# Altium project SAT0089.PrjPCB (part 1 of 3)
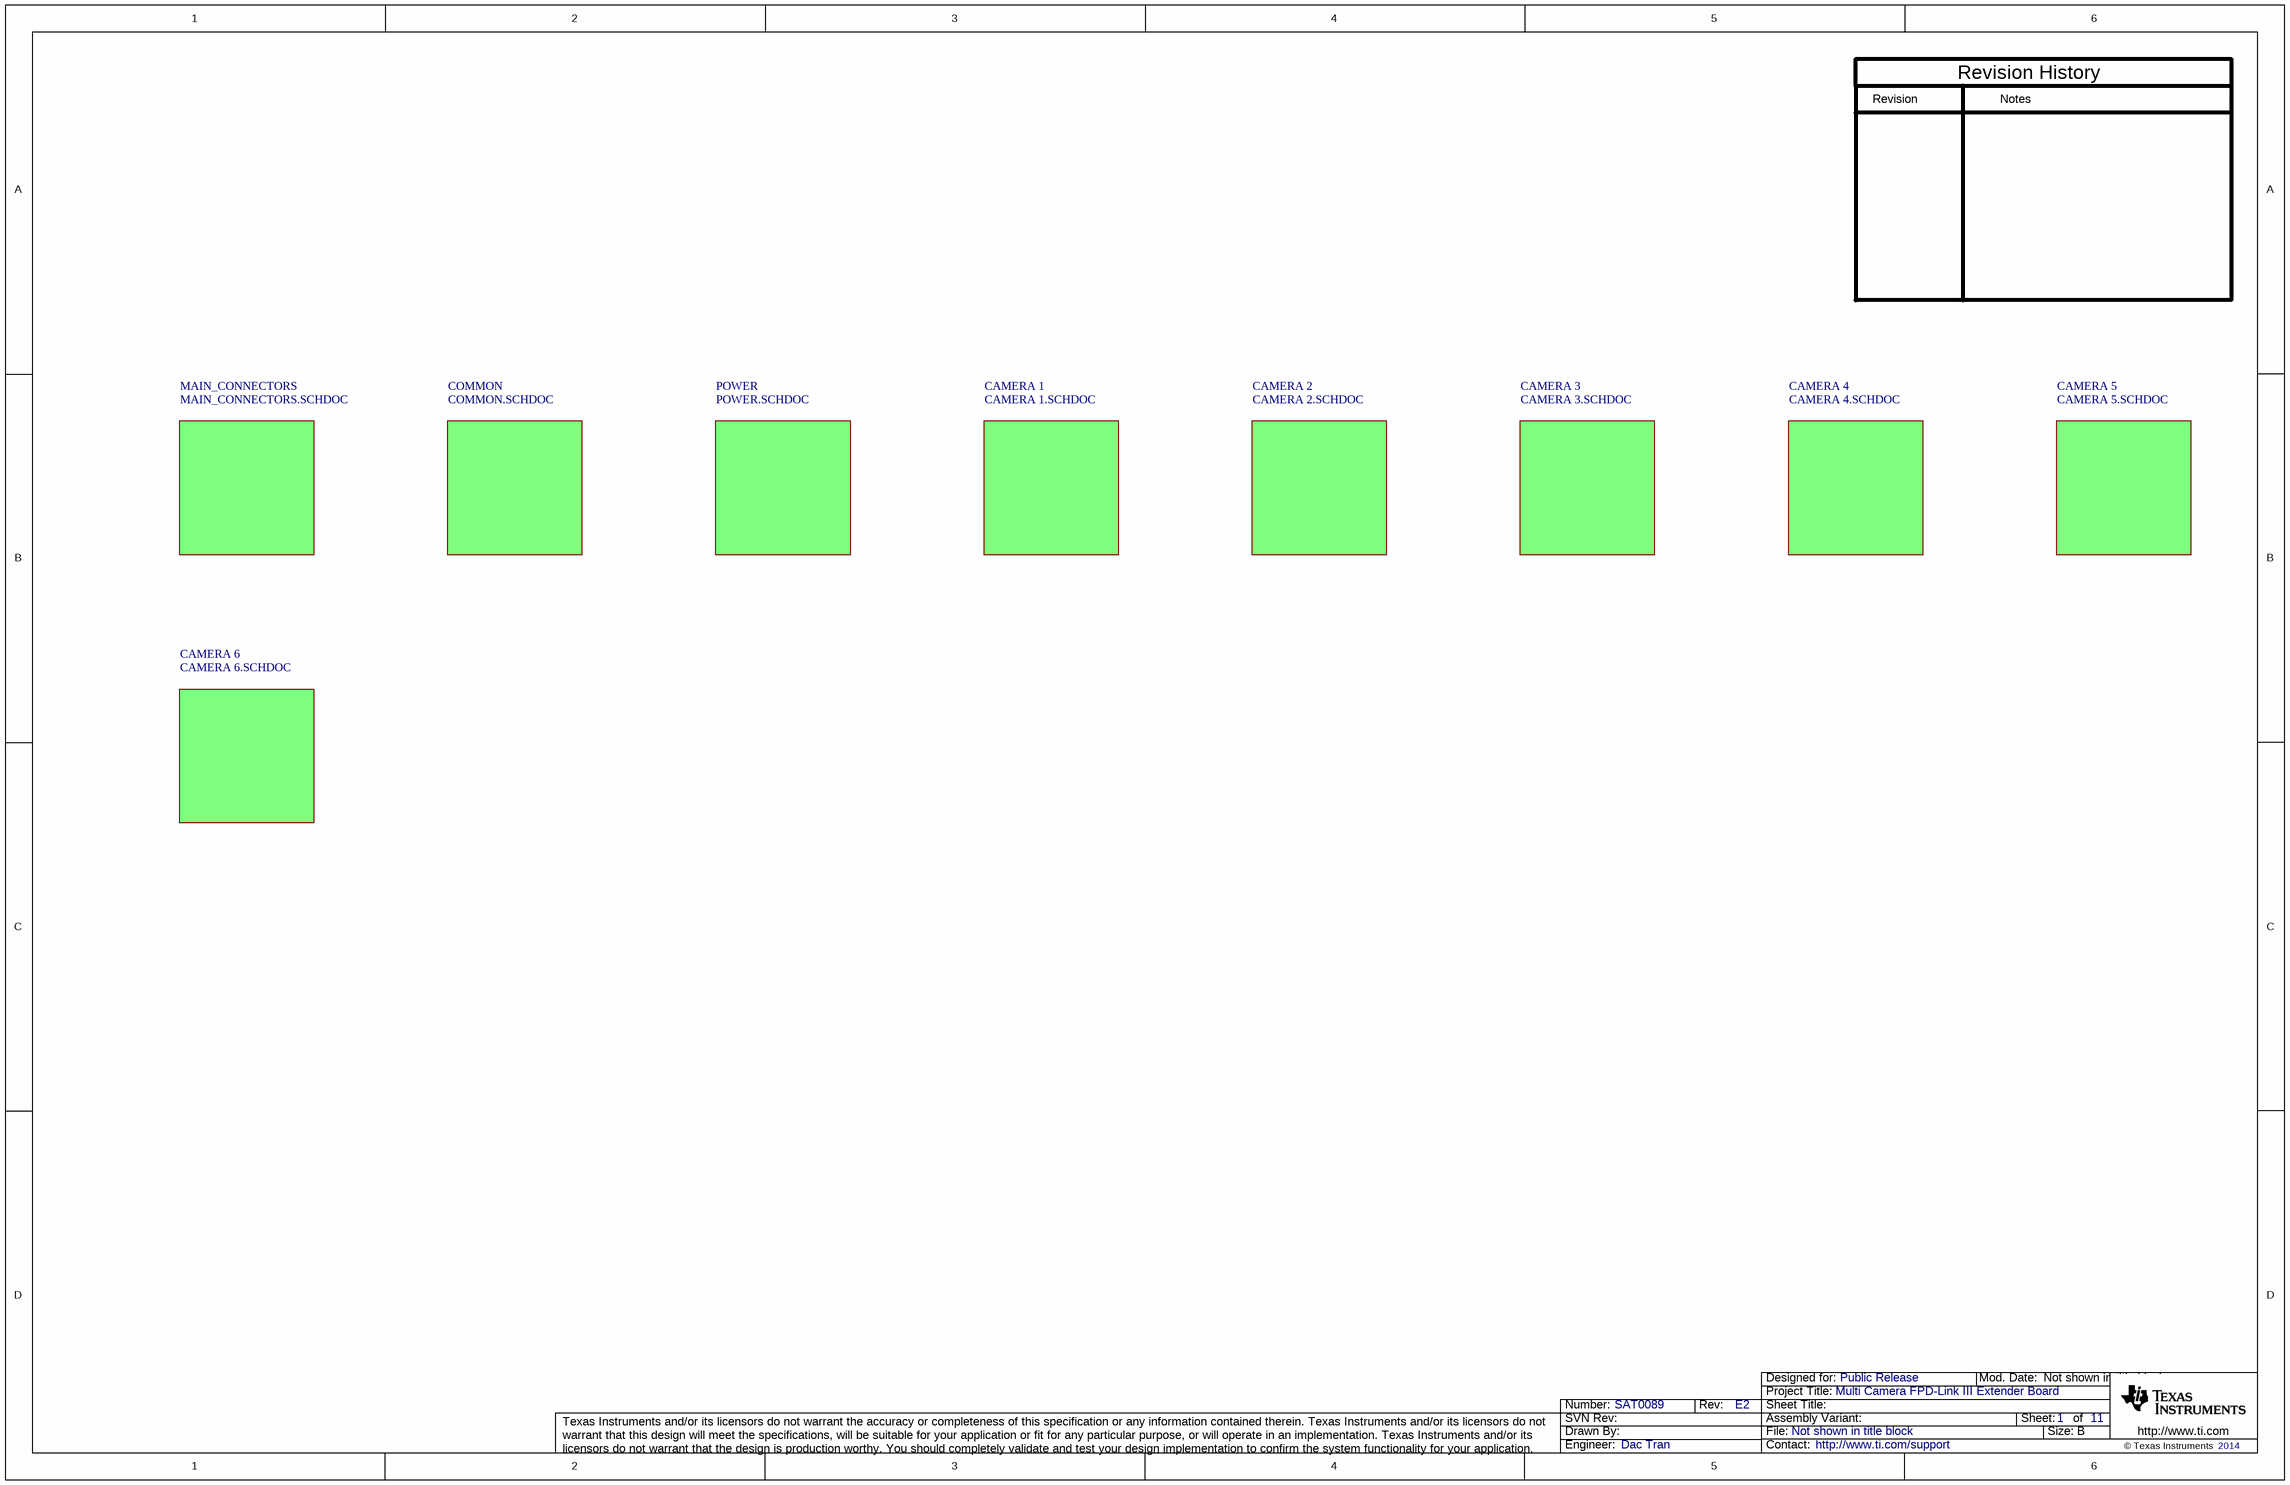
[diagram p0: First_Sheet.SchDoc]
TechSupport: http://www.ti.com/support; SCH_Rev: E2; PRJ_Title: Multi Camera FPD-Link III Extender Board; PRJ_Number: SAT0089; PRJ_Engineer: Dac Tran; PRJ_Customer: Public Release; PCB_Rev: E2; PCB_Layout: Krypton Solutions/RS; CopyrightYear: 2014
11 sheets, 539 parts. Net scope: flat (ports and power ports of the same name join across sheets).
Board file: SAT0089.PcbDoc
Sheets:
  First_Sheet.SchDoc
    POWER = POWER.SchDoc
    MAIN_CONNECTORS = MAIN_CONNECTORS.SchDoc
    COMMON = COMMON.SchDoc
    CAMERA 1 = CAMERA 1.SchDoc
    CAMERA 2 = CAMERA 2.SchDoc
    CAMERA 3 = CAMERA 3.SchDoc
    CAMERA 4 = CAMERA 4.SchDoc
    CAMERA 5 = CAMERA 5.SchDoc
    CAMERA 6 = CAMERA 6.SchDoc
  Hardware_ANSI-B.SchDoc

## Sheet First_Sheet.SchDoc
size 431 x 279 mm; Date: Not shown in title block; ApprovedBy: Not shown in title block; CheckedBy: Not shown in title block; Author: Not shown in title block; CompanyName: Not shown in title block; Engineer: Not shown in title block; Organization: Not shown in title block; Address1: Not shown in title block; Address2: Not shown in title block; Address3: Not shown in title block; Address4: Not shown in title block; DocumentNumber: 1; Revision: Use project parameter SCH_Rev; SheetNumber: 1; SheetTotal: 11; PageSetup: Record=PageOptions|CenterHorizontal=True|CenterVertical=True|PrintScale=1.00|XCorrection=1.00|YCorrection=1.00|PrintKind=0|BorderSize=5000000|LeftOffset=0|BottomOffset=0|Orientation=2|PaperLength=1000|PaperWidth=1000|Scale=100|PaperSource=15|PrintQuality=600|MediaType=1|DitherType=10|PaperKind=Letter|PrintScaleMode=1

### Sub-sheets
CAMERA 1 = CAMERA 1.SCHDOC: no entries
CAMERA 2 = CAMERA 2.SCHDOC: no entries
CAMERA 3 = CAMERA 3.SCHDOC: no entries
CAMERA 4 = CAMERA 4.SCHDOC: no entries
CAMERA 5 = CAMERA 5.SCHDOC: no entries
CAMERA 6 = CAMERA 6.SCHDOC: no entries
COMMON = COMMON.SCHDOC: no entries
MAIN_CONNECTORS = MAIN_CONNECTORS.SCHDOC: no entries
POWER = POWER.SCHDOC: no entries

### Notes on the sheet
- Revision
- Notes
- Revision History

## Sheet POWER.SchDoc
size 431 x 279 mm; Date: Not shown in title block; ApprovedBy: Not shown in title block; CheckedBy: Not shown in title block; Author: Not shown in title block; CompanyName: Not shown in title block; DrawnBy: G. Fiolic; Engineer: Not shown in title block; Organization: Not shown in title block; Address1: Not shown in title block; Address2: Not shown in title block; Address3: Not shown in title block; Address4: Not shown in title block; DocumentNumber: 4; Revision: Use project parameter SCH_Rev; SheetNumber: 4; SheetTotal: 11; PageSetup: Record=PageOptions|CenterHorizontal=True|CenterVertical=True|PrintScale=1.00|XCorrection=1.00|YCorrection=1.00|PrintKind=0|BorderSize=5000000|LeftOffset=0|BottomOffset=0|Orientation=2|PaperLength=1000|PaperWidth=1000|Scale=100|PaperSource=15|PrintQuality=600|MediaType=1|DitherType=10|PaperKind=Letter|PrintScaleMode=1
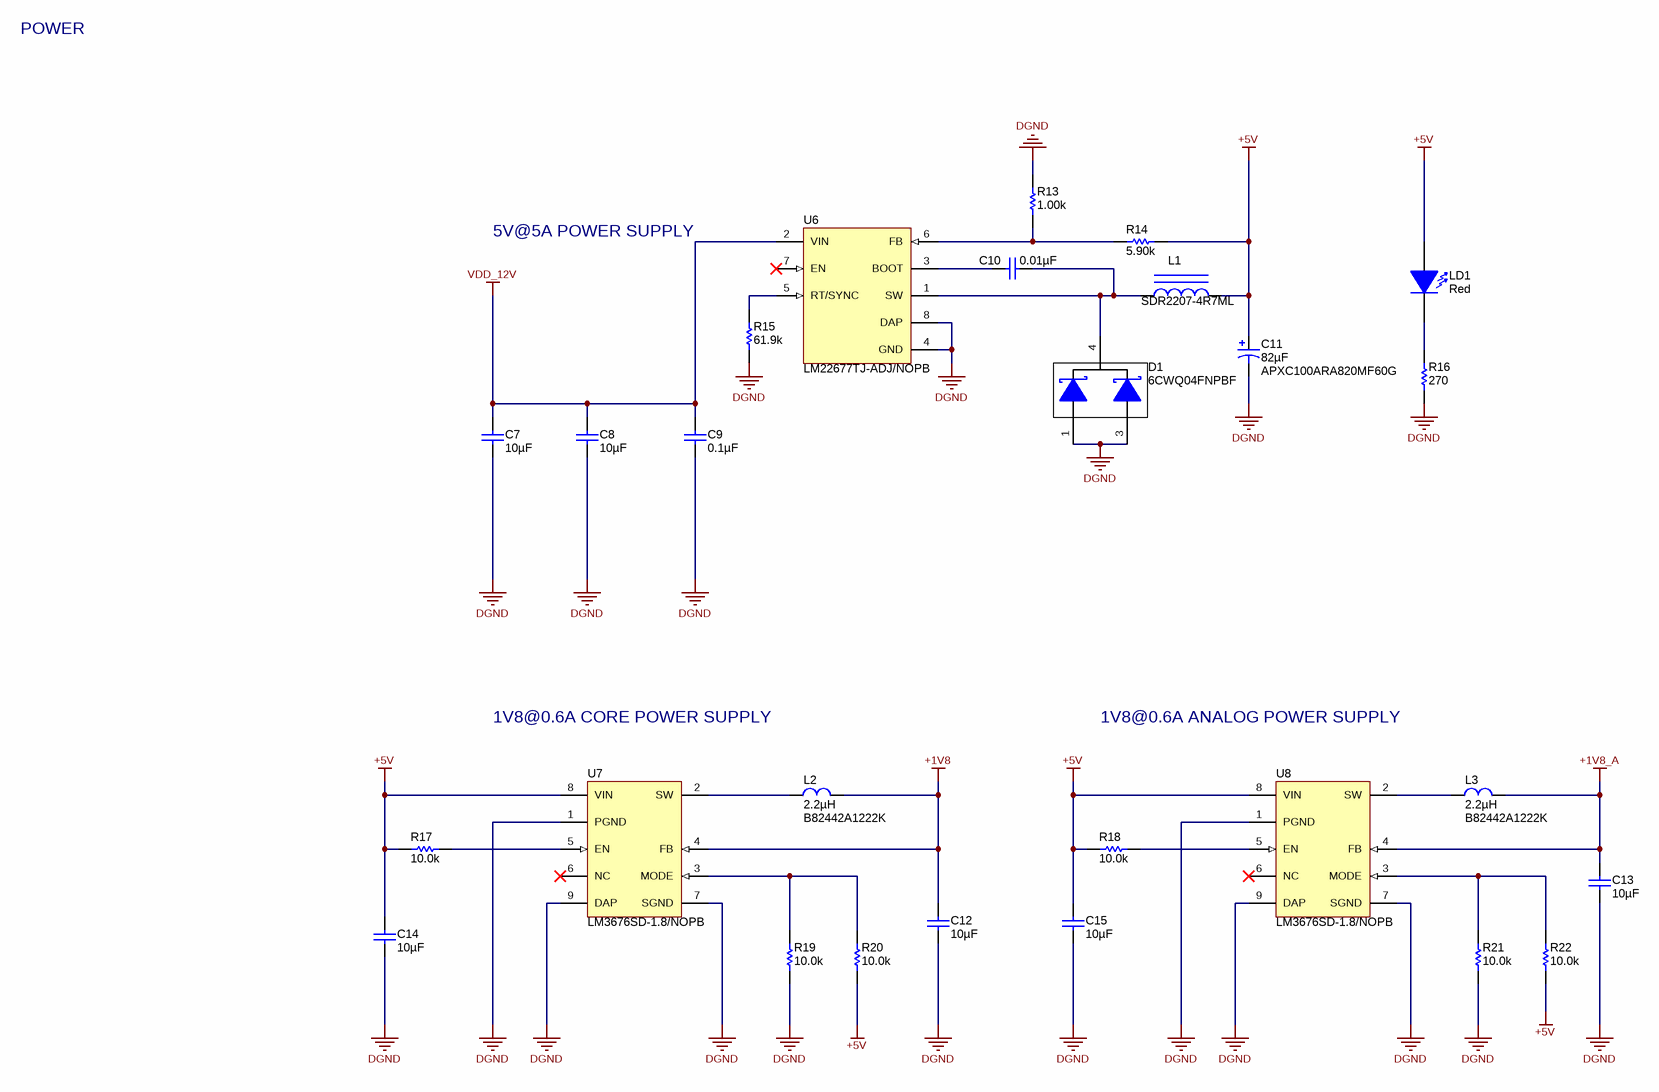
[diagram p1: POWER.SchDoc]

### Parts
C7  ValueDisplayed: 10µF  [1206L]  (hidden comment: GRM31CR71E106KA12L)
C8  ValueDisplayed: 10µF  [1206L]  (hidden comment: GRM31CR71E106KA12L)
C9  ValueDisplayed: 0.1µF  [0603L]  (hidden comment: GCM188R71H104KA57B)
C10  ValueDisplayed: 0.01µF  [0603L]  (hidden comment: GRM188R71H103KA01D)
C11  ValueDisplayed: 82µF  [CAPSMT_62_F60]  (hidden comment: APXC100ARA820MF60G)
C12  ValueDisplayed: 10µF  [0805L]  (hidden comment: GRM21BR71A106KE51L)
C13  ValueDisplayed: 10µF  [0805L]  (hidden comment: GRM21BR71A106KE51L)
C14  ValueDisplayed: 10µF  [0805L]  (hidden comment: GRM21BR71A106KE51L)
C15  ValueDisplayed: 10µF  [0805L]  (hidden comment: GRM21BR71A106KE51L)
D1  6CWQ04FNPBF  [DPAK]
L1  SDR2207-4R7ML  [SDR2207]
L2  ValueDisplayed: 2.2µH  [B82442A1222K]  (hidden comment: B82442A1222K)
L3  ValueDisplayed: 2.2µH  [B82442A1222K]  (hidden comment: B82442A1222K)
LD1  value Red  [LED_LTST-C190_Red]  (hidden comment: LTST-C190CKT)
R13  value 1.00k  [0402L]  (hidden comment: CRCW04021K00FKED)
R14  value 5.90k  [0603]  (hidden comment: CRCW06035K90FKEA)
R15  value 61.9k  [0402L]  (hidden comment: CRCW040261K9FKED)
R16  value 270  [0805L]  (hidden comment: CRCW0805270RJNEA)
R17  value 10.0k  [0402L]  (hidden comment: CRCW040210K0FKED)
R18  value 10.0k  [0402L]  (hidden comment: CRCW040210K0FKED)
R19  value 10.0k  [0402L]  (hidden comment: CRCW040210K0FKED)
R20  value 10.0k  [0402L]  (hidden comment: CRCW040210K0FKED)
R21  value 10.0k  [0402L]  (hidden comment: CRCW040210K0FKED)
R22  value 10.0k  [0402L]  (hidden comment: CRCW040210K0FKED)
U6  LM22677TJ-ADJ/NOPB  [TJ7A_N]
U7  LM3676SD-1.8/NOPB  [SDA08A]
U8  LM3676SD-1.8/NOPB  [SDA08A]

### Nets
+1V8: C12.1 L2.2 U7.4(FB)
+1V8_A: C13.1 L3.2 U8.4(FB)
+5V: C11.1(+) C14.1 C15.1 L1.2 LD1.1(A) R14.2 R17.2 R18.2 R20.2 R22.2 U7.8(VIN) U8.8(VIN)
DGND: C7.2 C8.2 C9.2 C11.2(-) C12.2 C13.2 C14.2 C15.2 D1.1(A) D1.3(A) R13.1 R15.2 R16.2 R19.2 R21.2 U6.4(GND) U6.8(DAP) U7.1(PGND) U7.7(SGND) U7.9(DAP) U8.1(PGND) U8.7(SGND) U8.9(DAP)
VDD_12V: C7.1 C8.1 C9.1 U6.2(VIN)
NetC10_1: C10.1 U6.3(BOOT)
NetC10_2: C10.2 D1.4(K) L1.1 U6.1(SW)
NetL2_1: L2.1 U7.2(SW)
NetL3_1: L3.1 U8.2(SW)
NetLD1_2: LD1.2(K) R16.1
NetR13_2: R13.2 R14.1 U6.6(FB)
NetR15_1: R15.1 U6.5(RT/SYNC)
NetR17_1: R17.1 U7.5(EN)
NetR18_1: R18.1 U8.5(EN)
NetR19_1: R19.1 R20.1 U7.3(MODE)
NetR21_1: R21.1 R22.1 U8.3(MODE)

Not connected (* = marked no-connect by the designer): U6 7(EN)*; U7 6(NC)*; U8 6(NC)*

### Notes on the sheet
- POWER
- 5V@5A POWER SUPPLY
- 1V8@0.6A CORE POWER SUPPLY
- 1V8@0.6A ANALOG POWER SUPPLY

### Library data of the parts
C7 C8 = GRM31CR71E106KA12L: CAP, CERM, 10uF, 25V, +/-10%, X7R, 1206; Manufacturer: MuRata; Polarized: N; CompType: Capacitor; U/M: EA; Cap_F: 0.00001; Tolerance_%: 10; Value1: Unknown; VDC_V: 25; TaMin_C: -55; TaMax_C: 125; Cap_Case: 2220
C9 = GCM188R71H104KA57B: CAP, CERM, 0.1uF, 50V, +/-10%, X7R, 0603; Manufacturer: MuRata; Polarized: N; CompType: Capacitor; U/M: EA; Cap_F: 0.0000001; Tolerance_%: 10; ESR_Ohm: 0.02; Value1: 0.02 ohm; VDC_V: 50; IRMS_A: 1.84; TaMin_C: -55; TaMax_C: 125; Cap_Case: 0603
C10 = GRM188R71H103KA01D: CAP, CERM, 0.01uF, 50V, +/-10%, X7R, 0603; Manufacturer: MuRata; Polarized: N; CompType: Capacitor; U/M: EA; Cap_F: 0.00000001; Tolerance_%: 10; Value1: Unknown; VDC_V: 50; TaMin_C: -55; TaMax_C: 125; Cap_Case: 0603
C11 = APXC100ARA820MF60G: CAP, AL, 82uF, 10V, +/-20%, 0.023 ohm, SMD; Manufacturer: Nippon Chemi-Con; Polarized: Y; CompType: Capacitor; U/M: EA; Cap_F: 0.000082; Tolerance_%: 20; VDC_V: 10; ESR_Ohm: 0.023; IRMS_A: 2.4; TaMin_C: -55; TaMax_C: 105; Cap_Case: F60
C12-C15 = GRM21BR71A106KE51L: CAP, CERM, 10uF, 10V, +/-10%, X7R, 0805; Manufacturer: MuRata; Polarized: N; CompType: Capacitor; U/M: EA; Cap_F: 0.00001; Tolerance_%: 10; ESR_Ohm: 0.003; Value1: 0.003 ohm; TaMin_C: -55; TaMax_C: 125; Cap_Case: 0805
D1 = 6CWQ04FNPBF: Diode, Schottky, 40V, 7A, DPAK; Manufacturer: Vishay-Semiconductor; U/M: EA; Vf_V: 0.67; Value2: 0.67V; Io_A: 7; Vr_V: 40; TJmax_C: 150; RJC_CperW: 2.35
L1 = SDR2207-4R7ML: Inductor, Drum Core, Ferrite, 4.7uH, 8.5A, 0.0088 ohm, SMD; Manufacturer: Bourns; Ind_H: 4.7E-6; ValueDisplayed: 4.7µH; Imax_A: 8.5; Irms: 8.5A @ 40C rise; Isat: 15A @ 10% inductance drop; DCR_ohm: 0.0088; U/M: EA
L2 L3 = B82442A1222K: INDUCTOR 2.2UH 1300MA 2220 10%; Manufacturer: EPCOS Inc; Type: Wirewound; Material - Core: Ferrite; Current Rating: 1.3A; Shielding: Unshielded; DCR_Ohm: 48 mOhm Max; Q @ Freq: 10 @ 7.96MHz; Frequency - Self Resonant: 42MHz; Frequency - Test: 7.96MHz
LD1 = LTST-C190CKT: LED, Red, SMD; Manufacturer: Lite-On; Vf_V: 2; Value2: 2V; Io_A: 0.02; Tjmax_C: 85; Power_TotalModule: 0.0625; Value1: 0.0625W; U/M: EA
R13 = CRCW04021K00FKED: RES, 1.00k ohm, 1%, 0.063W, 0402; Manufacturer: Vishay-Dale; CompType: Resistor; Res_ohm: 1000; Value_Code: 1k00; Tolerance_%: 1; Power_W: 0.063; VDC_V: 50; TempCo: 100 ppm/C; EIA_Code: E96; U/M: EA
R14 = CRCW06035K90FKEA: RES, 5.90k ohm, 1%, 0.1W, 0603; Manufacturer: Vishay-Dale; CompType: Resistor; Res_ohm: 5900; Value_Code: 5k90; Tolerance_%: 1; Power_W: 0.1; VDC_V: 75; TempCo: 100 ppm/C; EIA_Code: E96; U/M: EA
R15 = CRCW040261K9FKED: RES, 61.9k ohm, 1%, 0.063W, 0402; Manufacturer: Vishay-Dale; CompType: Resistor; Res_ohm: 61900; Value_Code: 61k9; Tolerance_%: 1; Power_W: 0.063; VDC_V: 50; TempCo: 100 ppm/C; EIA_Code: E96; U/M: EA
R16 = CRCW0805270RJNEA: RES, 270 ohm, 5%, 0.125W, 0805; Manufacturer: Vishay-Dale; CompType: Resistor; Value_Code: 270R; Tolerance_%: 5; Power_W: 0.125; VDC_V: 150; TempCo: 200 ppm/C; EIA_Code: E24; U/M: EA
R17-R22 = CRCW040210K0FKED: RES, 10.0k ohm, 1%, 0.063W, 0402; Manufacturer: Vishay-Dale; CompType: Resistor; Res_ohm: 10000; Value_Code: 10k0; Tolerance_%: 1; Power_W: 0.063; VDC_V: 50; TempCo: 100 ppm/C; EIA_Code: E96; U/M: EA
U6 = LM22677TJ-ADJ/NOPB: 5A SIMPLE SWITCHER®, Step-Down Voltage Regulator with Synchronization or Adjustable Switching Frequency, 7-pin TO-263 Thin, Pb-Free; Manufacturer: National Semiconductor; PackageTopMarking: NSUZXYTTE#*LM22677*TJ-ADJ; PowerWise: N
U7 U8 = LM3676SD-1.8/NOPB: 2MHz, 600mA Step-Down DC-DC Converter with Mode Control, 8-pin LLP, Pb-Free; Manufacturer: National Semiconductor; PackageTopMarking: ZXYTT*S009B; PowerWise: N; CompType: MiscPower

## Sheet MAIN_CONNECTORS.SchDoc
size 431 x 279 mm; Date: Not shown in title block; ApprovedBy: Not shown in title block; CheckedBy: Not shown in title block; Author: Not shown in title block; CompanyName: Not shown in title block; DrawnBy: G. Fiolic; Engineer: Not shown in title block; Organization: Not shown in title block; Address1: Not shown in title block; Address2: Not shown in title block; Address3: Not shown in title block; Address4: Not shown in title block; DocumentNumber: 2; Revision: Use project parameter SCH_Rev; SheetNumber: 2; SheetTotal: 11; PageSetup: Record=PageOptions|CenterHorizontal=True|CenterVertical=True|PrintScale=1.00|XCorrection=1.00|YCorrection=1.00|PrintKind=0|BorderSize=5000000|LeftOffset=0|BottomOffset=0|Orientation=2|PaperLength=1000|PaperWidth=1000|Scale=100|PaperSource=15|PrintQuality=600|MediaType=1|DitherType=10|PaperKind=Letter|PrintScaleMode=1
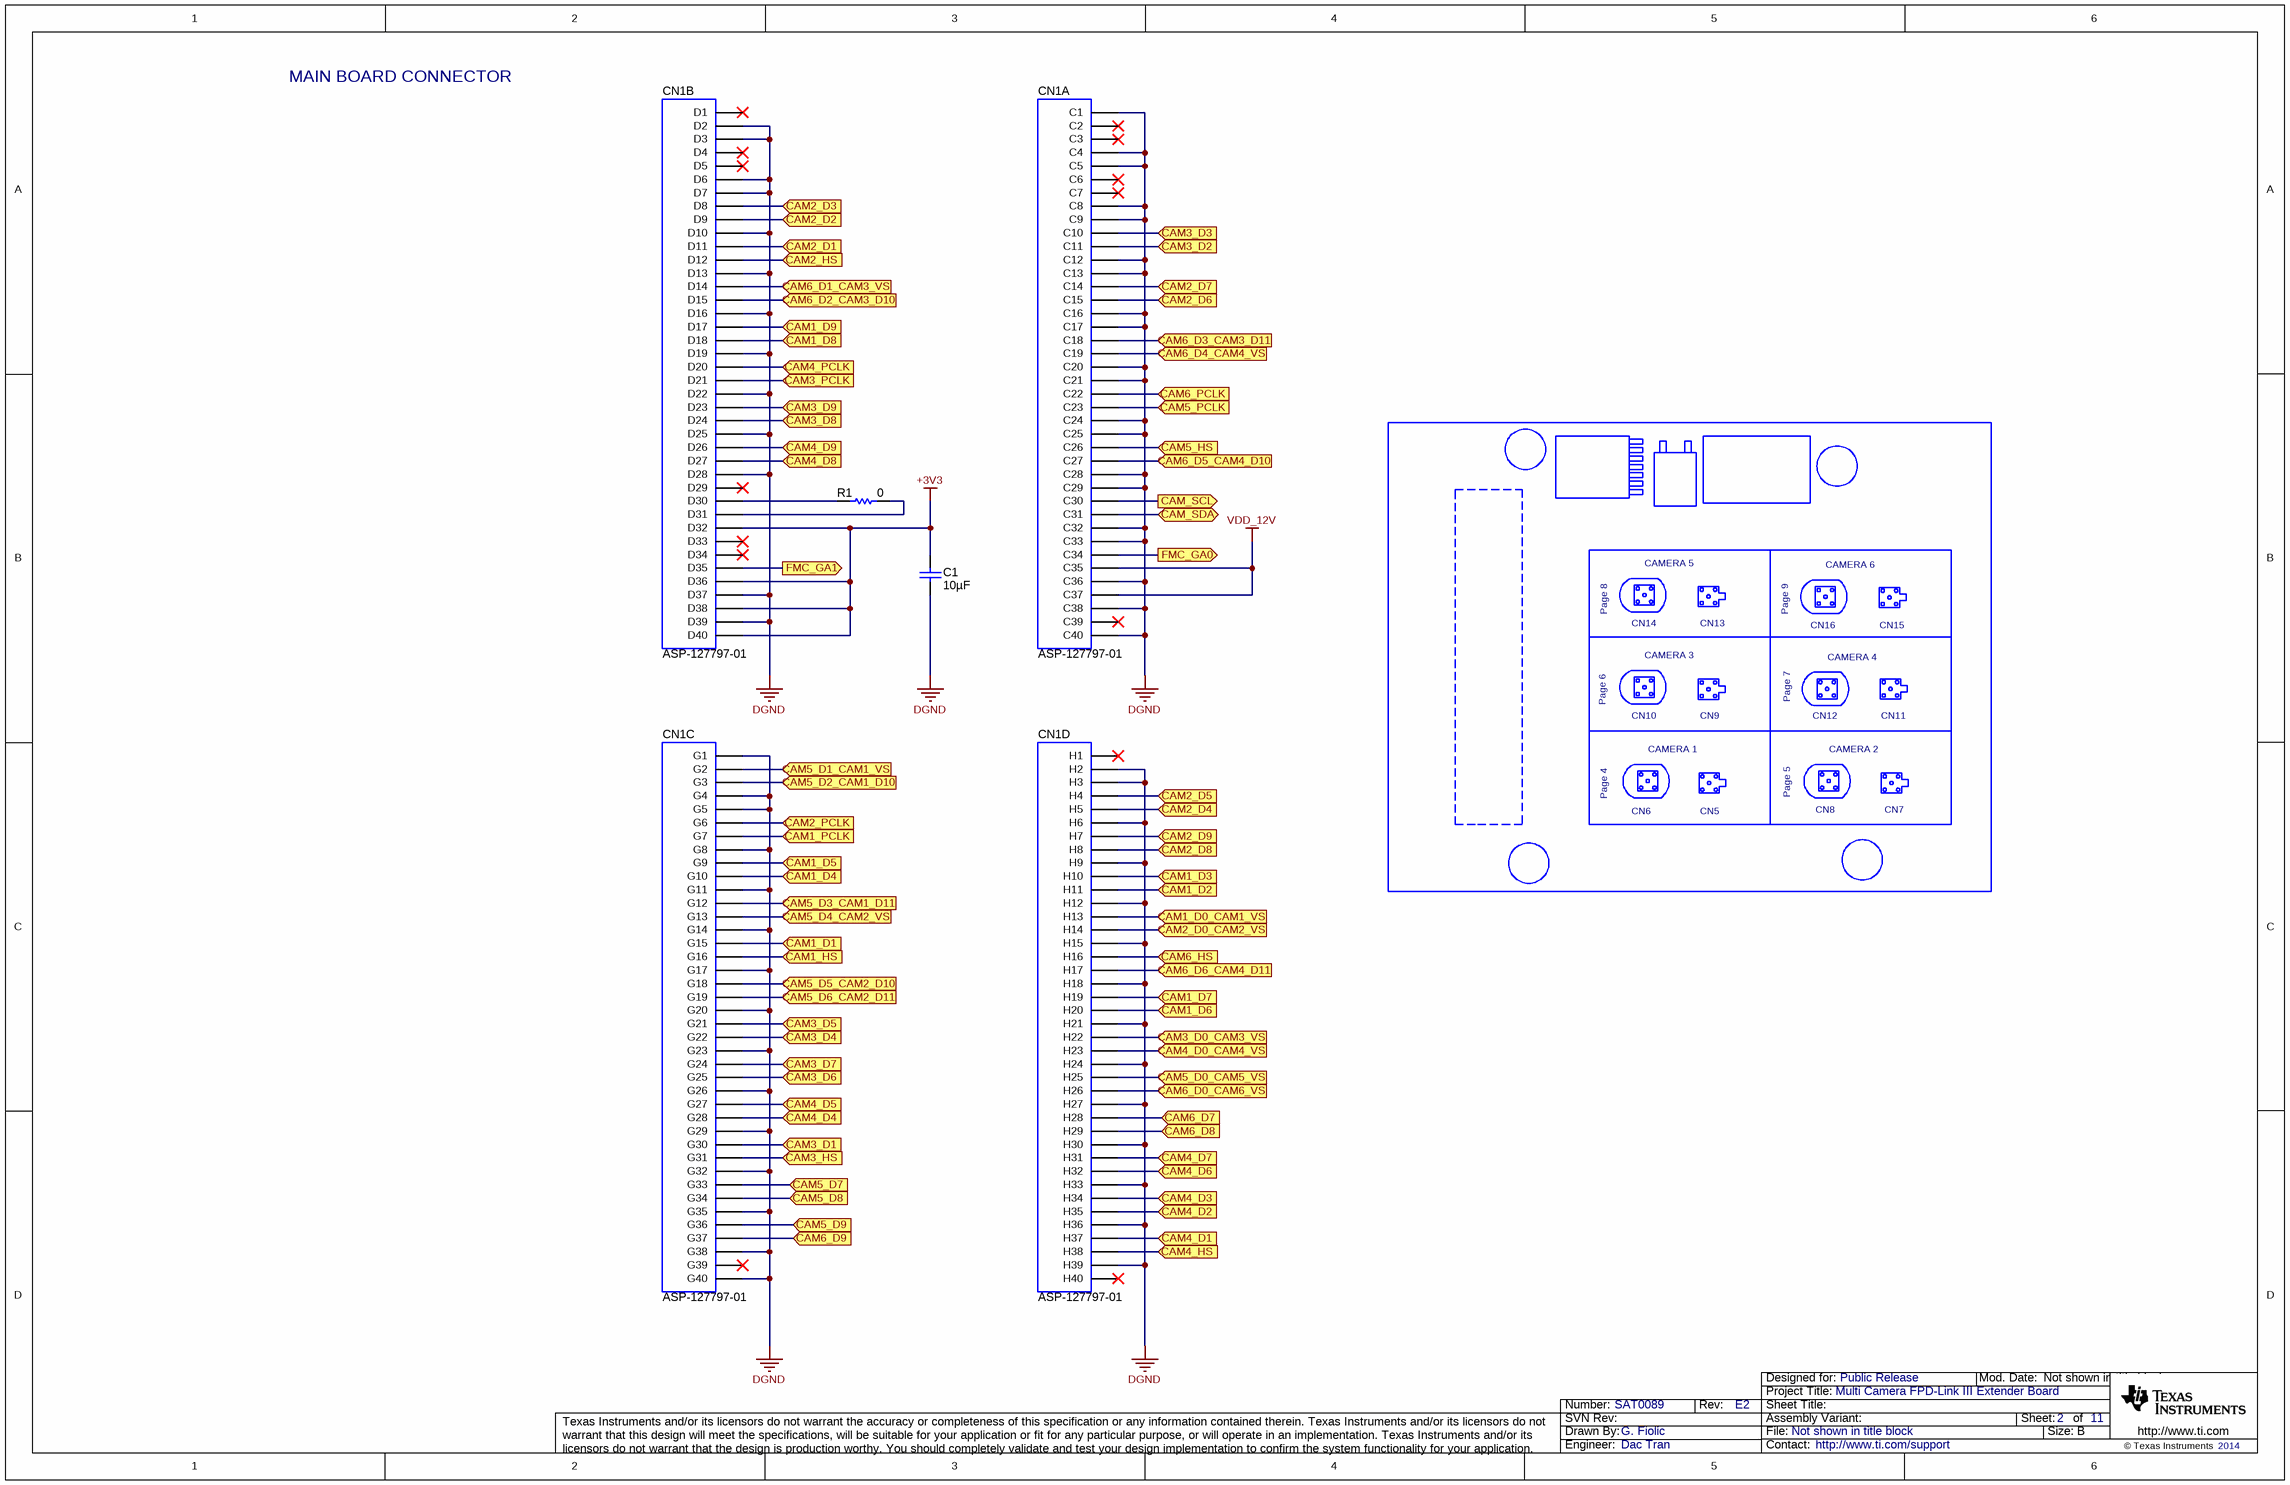
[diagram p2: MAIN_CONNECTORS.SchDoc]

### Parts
C1  ValueDisplayed: 10µF  [0805L]  (hidden comment: GRM21BR71A106KE51L)
CN1  ASP-127797-01  [ASP-127797-01]  (parts A,B,C,D of 4)
R1  value 0  [0402L]  (hidden comment: CRCW04020000Z0ED)

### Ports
CAM1_D0_CAM1_VS (in), CAM1_D1 (in), CAM1_D2 (in), CAM1_D3 (in), CAM1_D4 (in), CAM1_D5 (in), CAM1_D6 (in), CAM1_D7 (in), CAM1_D8 (in), CAM1_D9 (in), CAM1_HS (in), CAM1_PCLK (in), CAM2_D0_CAM2_VS (in), CAM2_D1 (in), CAM2_D2 (in), CAM2_D3 (in), CAM2_D4 (in), CAM2_D5 (in), CAM2_D6 (in), CAM2_D7 (in), CAM2_D8 (in), CAM2_D9 (in), CAM2_HS (in), CAM2_PCLK (in), CAM3_D0_CAM3_VS (in), CAM3_D1 (in), CAM3_D2 (in), CAM3_D3 (in), CAM3_D4 (in), CAM3_D5 (in), CAM3_D6 (in), CAM3_D7 (in), CAM3_D8 (in), CAM3_D9 (in), CAM3_HS (in), CAM3_PCLK (in), CAM4_D0_CAM4_VS (in), CAM4_D1 (in), CAM4_D2 (in), CAM4_D3 (in), CAM4_D4 (in), CAM4_D5 (in), CAM4_D6 (in), CAM4_D7 (in), CAM4_D8 (in), CAM4_D9 (in), CAM4_HS (in), CAM4_PCLK (in), CAM5_D0_CAM5_VS (in), CAM5_D1_CAM1_VS (in), CAM5_D2_CAM1_D10 (in), CAM5_D3_CAM1_D11 (in), CAM5_D4_CAM2_VS (in), CAM5_D5_CAM2_D10 (in), CAM5_D6_CAM2_D11 (in), CAM5_D7 (in), CAM5_D8 (in), CAM5_D9 (in), CAM5_HS (in), CAM5_PCLK (in), CAM6_D0_CAM6_VS (in), CAM6_D1_CAM3_VS (in), CAM6_D2_CAM3_D10 (in), CAM6_D3_CAM3_D11 (in), CAM6_D4_CAM4_VS (in), CAM6_D5_CAM4_D10 (in), CAM6_D6_CAM4_D11 (in), CAM6_D7 (in), CAM6_D8 (in), CAM6_D9 (in), CAM6_HS (in), CAM6_PCLK (in), CAM_SCL (out), CAM_SDA (bidir), FMC_GA0 (out), FMC_GA1 (out)

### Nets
+3V3: C1.1 CN1.72(D32) CN1.76(D36) CN1.78(D38) CN1.80(D40)
DGND: C1.2 CN1.1(C1) CN1.4(C4) CN1.5(C5) CN1.8(C8) CN1.9(C9) CN1.12(C12) CN1.13(C13) CN1.16(C16) CN1.17(C17) CN1.20(C20) CN1.21(C21) CN1.24(C24) CN1.25(C25) CN1.28(C28) CN1.29(C29) CN1.32(C32) CN1.33(C33) CN1.36(C36) CN1.38(C38) CN1.40(C40) CN1.42(D2) CN1.43(D3) CN1.46(D6) CN1.47(D7) CN1.50(D10) CN1.53(D13) CN1.56(D16) CN1.59(D19) CN1.62(D22) CN1.65(D25) CN1.68(D28) CN1.77(D37) CN1.79(D39) CN1.81(G1) CN1.84(G4) CN1.85(G5) CN1.88(G8) CN1.91(G11) CN1.94(G14) CN1.97(G17) CN1.100(G20) CN1.103(G23) CN1.106(G26) CN1.109(G29) CN1.112(G32) CN1.115(G35) CN1.118(G38) CN1.120(G40) CN1.122(H2) CN1.123(H3) CN1.126(H6) CN1.129(H9) CN1.132(H12) CN1.135(H15) CN1.138(H18) CN1.141(H21) CN1.144(H24) CN1.147(H27) CN1.150(H30) CN1.153(H33) CN1.156(H36) CN1.159(H39)
VDD_12V: CN1.35(C35) CN1.37(C37)
CAM1_D0_CAM1_VS: CN1.133(H13) ; port CAM1_D0_CAM1_VS
CAM1_D1: CN1.95(G15) ; port CAM1_D1
CAM1_D2: CN1.131(H11) ; port CAM1_D2
CAM1_D3: CN1.130(H10) ; port CAM1_D3
CAM1_D4: CN1.90(G10) ; port CAM1_D4
CAM1_D5: CN1.89(G9) ; port CAM1_D5
CAM1_D6: CN1.140(H20) ; port CAM1_D6
CAM1_D7: CN1.139(H19) ; port CAM1_D7
CAM1_D8: CN1.58(D18) ; port CAM1_D8
CAM1_D9: CN1.57(D17) ; port CAM1_D9
CAM1_HS: CN1.96(G16) ; port CAM1_HS
CAM1_PCLK: CN1.87(G7) ; port CAM1_PCLK
CAM2_D0_CAM2_VS: CN1.134(H14) ; port CAM2_D0_CAM2_VS
CAM2_D1: CN1.51(D11) ; port CAM2_D1
CAM2_D2: CN1.49(D9) ; port CAM2_D2
CAM2_D3: CN1.48(D8) ; port CAM2_D3
CAM2_D4: CN1.125(H5) ; port CAM2_D4
CAM2_D5: CN1.124(H4) ; port CAM2_D5
CAM2_D6: CN1.15(C15) ; port CAM2_D6
CAM2_D7: CN1.14(C14) ; port CAM2_D7
CAM2_D8: CN1.128(H8) ; port CAM2_D8
CAM2_D9: CN1.127(H7) ; port CAM2_D9
CAM2_HS: CN1.52(D12) ; port CAM2_HS
CAM2_PCLK: CN1.86(G6) ; port CAM2_PCLK
CAM3_D0_CAM3_VS: CN1.142(H22) ; port CAM3_D0_CAM3_VS
CAM3_D1: CN1.110(G30) ; port CAM3_D1
CAM3_D2: CN1.11(C11) ; port CAM3_D2
CAM3_D3: CN1.10(C10) ; port CAM3_D3
CAM3_D4: CN1.102(G22) ; port CAM3_D4
CAM3_D5: CN1.101(G21) ; port CAM3_D5
CAM3_D6: CN1.105(G25) ; port CAM3_D6
CAM3_D7: CN1.104(G24) ; port CAM3_D7
CAM3_D8: CN1.64(D24) ; port CAM3_D8
CAM3_D9: CN1.63(D23) ; port CAM3_D9
CAM3_HS: CN1.111(G31) ; port CAM3_HS
CAM3_PCLK: CN1.61(D21) ; port CAM3_PCLK
CAM4_D0_CAM4_VS: CN1.143(H23) ; port CAM4_D0_CAM4_VS
CAM4_D1: CN1.157(H37) ; port CAM4_D1
CAM4_D2: CN1.155(H35) ; port CAM4_D2
CAM4_D3: CN1.154(H34) ; port CAM4_D3
CAM4_D4: CN1.108(G28) ; port CAM4_D4
CAM4_D5: CN1.107(G27) ; port CAM4_D5
CAM4_D6: CN1.152(H32) ; port CAM4_D6
CAM4_D7: CN1.151(H31) ; port CAM4_D7
CAM4_D8: CN1.67(D27) ; port CAM4_D8
CAM4_D9: CN1.66(D26) ; port CAM4_D9
CAM4_HS: CN1.158(H38) ; port CAM4_HS
CAM4_PCLK: CN1.60(D20) ; port CAM4_PCLK
CAM5_D0_CAM5_VS: CN1.145(H25) ; port CAM5_D0_CAM5_VS
CAM5_D1_CAM1_VS: CN1.82(G2) ; port CAM5_D1_CAM1_VS
CAM5_D2_CAM1_D10: CN1.83(G3) ; port CAM5_D2_CAM1_D10
CAM5_D3_CAM1_D11: CN1.92(G12) ; port CAM5_D3_CAM1_D11
CAM5_D4_CAM2_VS: CN1.93(G13) ; port CAM5_D4_CAM2_VS
CAM5_D5_CAM2_D10: CN1.98(G18) ; port CAM5_D5_CAM2_D10
CAM5_D6_CAM2_D11: CN1.99(G19) ; port CAM5_D6_CAM2_D11
CAM5_D7: CN1.113(G33) ; port CAM5_D7
CAM5_D8: CN1.114(G34) ; port CAM5_D8
CAM5_D9: CN1.116(G36) ; port CAM5_D9
CAM5_HS: CN1.26(C26) ; port CAM5_HS
CAM5_PCLK: CN1.23(C23) ; port CAM5_PCLK
CAM6_D0_CAM6_VS: CN1.146(H26) ; port CAM6_D0_CAM6_VS
CAM6_D1_CAM3_VS: CN1.54(D14) ; port CAM6_D1_CAM3_VS
CAM6_D2_CAM3_D10: CN1.55(D15) ; port CAM6_D2_CAM3_D10
CAM6_D3_CAM3_D11: CN1.18(C18) ; port CAM6_D3_CAM3_D11
CAM6_D4_CAM4_VS: CN1.19(C19) ; port CAM6_D4_CAM4_VS
CAM6_D5_CAM4_D10: CN1.27(C27) ; port CAM6_D5_CAM4_D10
CAM6_D6_CAM4_D11: CN1.137(H17) ; port CAM6_D6_CAM4_D11
CAM6_D7: CN1.148(H28) ; port CAM6_D7
CAM6_D8: CN1.149(H29) ; port CAM6_D8
CAM6_D9: CN1.117(G37) ; port CAM6_D9
CAM6_HS: CN1.136(H16) ; port CAM6_HS
CAM6_PCLK: CN1.22(C22) ; port CAM6_PCLK
CAM_SCL: CN1.30(C30) ; port CAM_SCL
CAM_SDA: CN1.31(C31) ; port CAM_SDA
FMC_GA0: CN1.34(C34) ; port FMC_GA0
FMC_GA1: CN1.75(D35) ; port FMC_GA1
NetCN1_70: CN1.70(D30) R1.2
NetCN1_71: CN1.71(D31) R1.1

Not connected (* = marked no-connect by the designer): CN1 2(C2)* 3(C3)* 6(C6)* 7(C7)* 39(C39)* 41(D1)* 44(D4)* 45(D5)* 69(D29)* 73(D33)* 74(D34)* 119(G39)* 121(H1)* 160(H40)*

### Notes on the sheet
- MAIN BOARD CONNECTOR
- CAMERA 5
- CAMERA 6
- Page 8
- CN14
- CN13
- Page 9
- CN16
- CN15
- Page 6
- CAMERA 3
- Page 7
- CAMERA 4
- CN10
- CAMERA 1
- CN9
- CN12
- CAMERA 2
- CN11
- Page 4
- CN6
- CN5
- Page 5
- CN8
- CN7

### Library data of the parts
C1 = GRM21BR71A106KE51L: as C12 on sheet POWER
CN1 = ASP-127797-01: Samtec 50 MIL Pitch Thermal Array Assembly; SymbolVersion: use current date i.e. 2008-05-20; SymbolCreator: Use a-id; CompType: Connector; U/M: EA, IN, or GM
R1 = CRCW04020000Z0ED: RES, 0 ohm, 5%, 0.063W, 0402; Manufacturer: Vishay-Dale; CompType: Resistor; Value_Code: 0000; Tolerance_%: 5; Power_W: 0.063; VDC_V: 50; TempCo: 200 ppm/C; EIA_Code: E24; U/M: EA

## Sheet COMMON.SchDoc
size 431 x 279 mm; Date: Not shown in title block; ApprovedBy: Not shown in title block; CheckedBy: Not shown in title block; Author: Not shown in title block; CompanyName: Not shown in title block; DrawnBy: G. Fiolic; Engineer: Not shown in title block; Organization: Not shown in title block; Address1: Not shown in title block; Address2: Not shown in title block; Address3: Not shown in title block; Address4: Not shown in title block; DocumentNumber: 3; Revision: Use project parameter SCH_Rev; SheetNumber: 3; SheetTotal: 11; PageSetup: Record=PageOptions|CenterHorizontal=True|CenterVertical=True|PrintScale=1.00|XCorrection=1.00|YCorrection=1.00|PrintKind=0|BorderSize=5000000|LeftOffset=0|BottomOffset=0|Orientation=2|PaperLength=1000|PaperWidth=1000|Scale=100|PaperSource=15|PrintQuality=600|MediaType=1|DitherType=10|PaperKind=Letter|PrintScaleMode=1
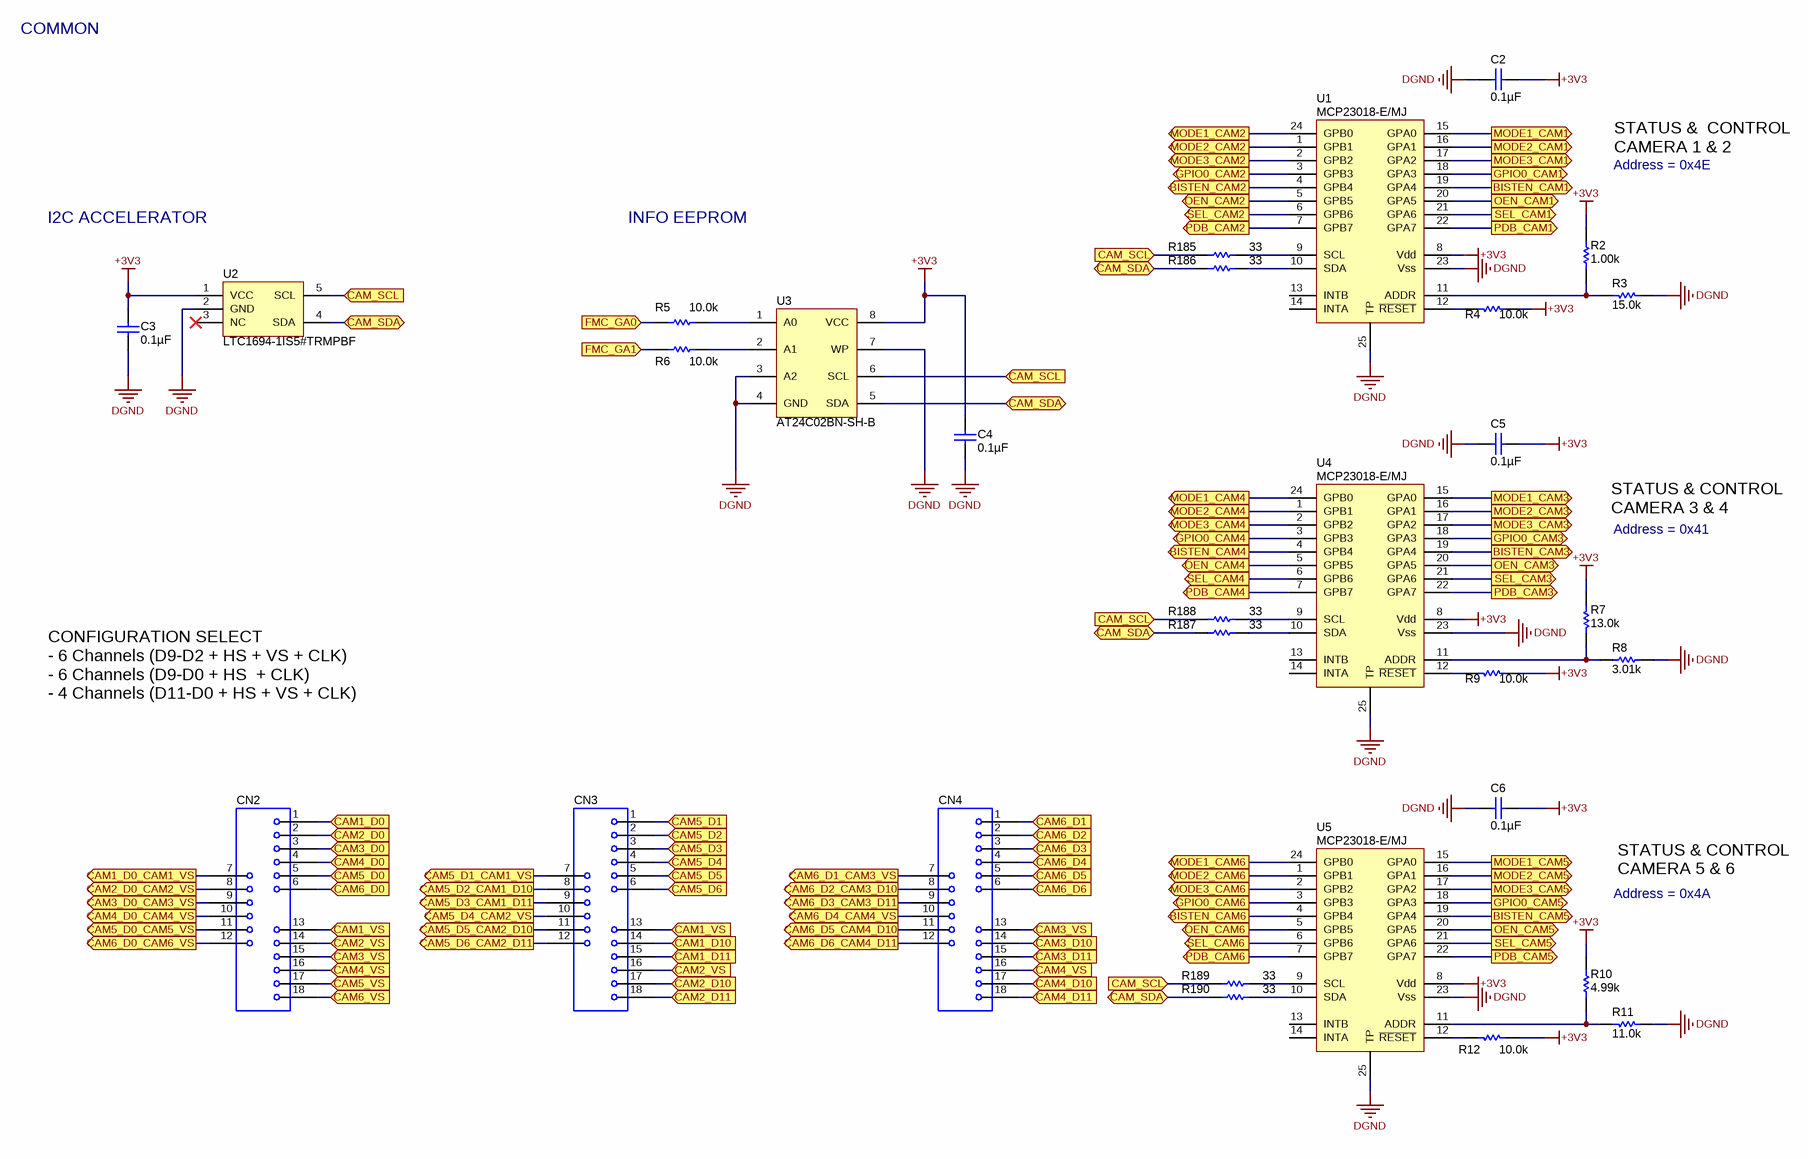
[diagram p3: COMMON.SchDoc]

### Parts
C2  ValueDisplayed: 0.1µF  [0402L]  (hidden comment: GRM155R71C104KA88D)
C3  ValueDisplayed: 0.1µF  [0402L]  (hidden comment: GRM155R71C104KA88D)
C4  ValueDisplayed: 0.1µF  [0402L]  (hidden comment: GRM155R71C104KA88D)
C5  ValueDisplayed: 0.1µF  [0402L]  (hidden comment: GRM155R71C104KA88D)
C6  ValueDisplayed: 0.1µF  [0402L]  (hidden comment: GRM155R71C104KA88D)
CN2  STD  [3X6 Header 100 MIL PITCH]  (value not drawn)
CN3  STD  [3X6 Header 100 MIL PITCH]  (value not drawn)
CN4  STD  [3X6 Header 100 MIL PITCH]  (value not drawn)
R2  value 1.00k  [0402L]  (hidden comment: CRCW04021K00FKED)
R3  value 15.0k  [0402L]  (hidden comment: CRCW040215K0FKED)
R4  value 10.0k  [0402L]  (hidden comment: CRCW040210K0FKED)
R5  value 10.0k  [0402L]  (hidden comment: CRCW040210K0FKED)
R6  value 10.0k  [0402L]  (hidden comment: CRCW040210K0FKED)
R7  value 13.0k  [0402L]  (hidden comment: CRCW040213K0FKED)
R8  value 3.01k  [0402L]  (hidden comment: CRCW04023K01FKED)
R9  value 10.0k  [0402L]  (hidden comment: CRCW040210K0FKED)
R10  value 4.99k  [0402L]  (hidden comment: CRCW04024K99FKED)
R11  value 11.0k  [0402L]  (hidden comment: CRCW040211K0FKED)
R12  value 10.0k  [0402L]  (hidden comment: CRCW040210K0FKED)
R185  value 33  [0402L]  (hidden comment: CRCW040233R0JNED)
R186  value 33  [0402L]  (hidden comment: CRCW040233R0JNED)
R187  value 33  [0402L]  (hidden comment: CRCW040233R0JNED)
R188  value 33  [0402L]  (hidden comment: CRCW040233R0JNED)
R189  value 33  [0402L]  (hidden comment: CRCW040233R0JNED)
R190  value 33  [0402L]  (hidden comment: CRCW040233R0JNED)
U1  MCP23018-E/MJ  [MCP23018-E/MJ]
U2  LTC1694-1IS5#TRMPBF  [LTC1694-1IS5#TRMPBF]
U3  AT24C02BN-SH-B  [AT24C02BN-SH-B]
U4  MCP23018-E/MJ  [MCP23018-E/MJ]
U5  MCP23018-E/MJ  [MCP23018-E/MJ]

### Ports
BISTEN_CAM1 (out), BISTEN_CAM2 (out), BISTEN_CAM3 (out), BISTEN_CAM4 (out), BISTEN_CAM5 (out), BISTEN_CAM6 (out), CAM1_D0 (in), CAM1_D0_CAM1_VS (out), CAM1_D10 (in), CAM1_D11 (in), CAM1_VS (in), CAM2_D0 (in), CAM2_D0_CAM2_VS (out), CAM2_D10 (in), CAM2_D11 (in), CAM2_VS (in), CAM3_D0 (in), CAM3_D0_CAM3_VS (out), CAM3_D10 (in), CAM3_D11 (in), CAM3_VS (in), CAM4_D0 (in), CAM4_D0_CAM4_VS (out), CAM4_D10 (in), CAM4_D11 (in), CAM4_VS (in), CAM5_D0 (in), CAM5_D0_CAM5_VS (out), CAM5_D1 (in), CAM5_D1_CAM1_VS (out), CAM5_D2 (in), CAM5_D2_CAM1_D10 (out), CAM5_D3 (in), CAM5_D3_CAM1_D11 (out), CAM5_D4 (in), CAM5_D4_CAM2_VS (out), CAM5_D5 (in), CAM5_D5_CAM2_D10 (out), CAM5_D6 (in), CAM5_D6_CAM2_D11 (out), CAM5_VS (in), CAM6_D0 (in), CAM6_D0_CAM6_VS (out), CAM6_D1 (in), CAM6_D1_CAM3_VS (out), CAM6_D2 (in), CAM6_D2_CAM3_D10 (out), CAM6_D3 (in), CAM6_D3_CAM3_D11 (out), CAM6_D4 (in), CAM6_D4_CAM4_VS (out), CAM6_D5 (in), CAM6_D5_CAM4_D10 (out), CAM6_D6 (in), CAM6_D6_CAM4_D11 (out), CAM6_VS (in), CAM_SCL (in), CAM_SDA (bidir), FMC_GA0 (in), FMC_GA1 (in), GPIO0_CAM1 (out), GPIO0_CAM2 (out), GPIO0_CAM3 (out), GPIO0_CAM4 (out), GPIO0_CAM5 (out), GPIO0_CAM6 (out), MODE1_CAM1 (out), MODE1_CAM2 (out), MODE1_CAM3 (out), MODE1_CAM4 (out), MODE1_CAM5 (out), MODE1_CAM6 (out), MODE2_CAM1 (out), MODE2_CAM2 (out), MODE2_CAM3 (out), MODE2_CAM4 (out), MODE2_CAM5 (out), MODE2_CAM6 (out), MODE3_CAM1 (out), MODE3_CAM2 (out), MODE3_CAM3 (out), MODE3_CAM4 (out), MODE3_CAM5 (out), MODE3_CAM6 (out), OEN_CAM1 (out), OEN_CAM2 (out), OEN_CAM3 (out), OEN_CAM4 (out), OEN_CAM5 (out), OEN_CAM6 (out), PDB_CAM1 (out), PDB_CAM2 (out), PDB_CAM3 (out), PDB_CAM4 (out), PDB_CAM5 (out), PDB_CAM6 (out), SEL_CAM1 (out), SEL_CAM2 (out), SEL_CAM3 (out), SEL_CAM4 (out), SEL_CAM5 (out), SEL_CAM6 (out)

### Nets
+3V3: C2.2 C3.1 C4.1 C5.2 C6.2 R2.2 R4.2 R7.2 R9.2 R10.2 R12.2 U1.8(Vdd) U2.1(VCC) U3.8(VCC) U4.8(Vdd) U5.8(Vdd)
DGND: C2.1 C3.2 C4.2 C5.1 C6.1 R3.2 R8.2 R11.2 U1.23(Vss) U1.25(TP) U2.2(GND) U3.3(A2) U3.4(GND) U3.7(WP) U4.23(Vss) U4.25(TP) U5.23(Vss) U5.25(TP)
BISTEN_CAM1: U1.19(GPA4) ; port BISTEN_CAM1
BISTEN_CAM2: U1.4(GPB4) ; port BISTEN_CAM2
BISTEN_CAM3: U4.19(GPA4) ; port BISTEN_CAM3
BISTEN_CAM4: U4.4(GPB4) U4.6(GPB6) ; port BISTEN_CAM4, port SEL_CAM4
BISTEN_CAM5: U5.19(GPA4) ; port BISTEN_CAM5
BISTEN_CAM6: U5.4(GPB4) ; port BISTEN_CAM6
CAM1_D0: CN2.1 ; port CAM1_D0
CAM1_D0_CAM1_VS: CN2.7 ; port CAM1_D0_CAM1_VS
CAM1_D10: CN3.14 ; port CAM1_D10
CAM1_D11: CN3.15 ; port CAM1_D11
CAM1_VS: CN2.13 CN3.13 ; port CAM1_VS
CAM2_D0: CN2.2 ; port CAM2_D0
CAM2_D0_CAM2_VS: CN2.8 ; port CAM2_D0_CAM2_VS
CAM2_D10: CN3.17 ; port CAM2_D10
CAM2_D11: CN3.18 ; port CAM2_D11
CAM2_VS: CN2.14 CN3.16 ; port CAM2_VS
CAM3_D0: CN2.3 ; port CAM3_D0
CAM3_D0_CAM3_VS: CN2.9 ; port CAM3_D0_CAM3_VS
CAM3_D10: CN4.14 ; port CAM3_D10
CAM3_D11: CN4.15 ; port CAM3_D11
CAM3_VS: CN2.15 CN4.13 ; port CAM3_VS
CAM4_D0: CN2.4 ; port CAM4_D0
CAM4_D0_CAM4_VS: CN2.10 ; port CAM4_D0_CAM4_VS
CAM4_D10: CN4.17 ; port CAM4_D10
CAM4_D11: CN4.18 ; port CAM4_D11
CAM4_VS: CN2.16 CN4.16 ; port CAM4_VS
CAM5_D0: CN2.5 ; port CAM5_D0
CAM5_D0_CAM5_VS: CN2.11 ; port CAM5_D0_CAM5_VS
CAM5_D1: CN3.1 ; port CAM5_D1
CAM5_D1_CAM1_VS: CN3.7 ; port CAM5_D1_CAM1_VS
CAM5_D2: CN3.2 ; port CAM5_D2
CAM5_D2_CAM1_D10: CN3.8 ; port CAM5_D2_CAM1_D10
CAM5_D3: CN3.3 ; port CAM5_D3
CAM5_D3_CAM1_D11: CN3.9 ; port CAM5_D3_CAM1_D11
CAM5_D4: CN3.4 ; port CAM5_D4
CAM5_D4_CAM2_VS: CN3.10 ; port CAM5_D4_CAM2_VS
CAM5_D5: CN3.5 ; port CAM5_D5
CAM5_D5_CAM2_D10: CN3.11 ; port CAM5_D5_CAM2_D10
CAM5_D6: CN3.6 ; port CAM5_D6
CAM5_D6_CAM2_D11: CN3.12 ; port CAM5_D6_CAM2_D11
CAM5_VS: CN2.17 ; port CAM5_VS
CAM6_D0: CN2.6 ; port CAM6_D0
CAM6_D0_CAM6_VS: CN2.12 ; port CAM6_D0_CAM6_VS
CAM6_D1: CN4.1 ; port CAM6_D1
CAM6_D1_CAM3_VS: CN4.7 ; port CAM6_D1_CAM3_VS
CAM6_D2: CN4.2 ; port CAM6_D2
CAM6_D2_CAM3_D10: CN4.8 ; port CAM6_D2_CAM3_D10
CAM6_D3: CN4.3 ; port CAM6_D3
CAM6_D3_CAM3_D11: CN4.9 ; port CAM6_D3_CAM3_D11
CAM6_D4: CN4.4 ; port CAM6_D4
CAM6_D4_CAM4_VS: CN4.10 ; port CAM6_D4_CAM4_VS
CAM6_D5: CN4.5 ; port CAM6_D5
CAM6_D5_CAM4_D10: CN4.11 ; port CAM6_D5_CAM4_D10
CAM6_D6: CN4.6 ; port CAM6_D6
CAM6_D6_CAM4_D11: CN4.12 ; port CAM6_D6_CAM4_D11
CAM6_VS: CN2.18 ; port CAM6_VS
CAM_SCL: R185.2 R188.2 R189.2 U2.5(SCL) U3.6(SCL) ; port CAM_SCL
CAM_SDA: R186.2 R187.2 R190.2 U2.4(SDA) U3.5(SDA) ; port CAM_SDA
FMC_GA0: R5.1 ; port FMC_GA0
FMC_GA1: R6.2 ; port FMC_GA1
GPIO0_CAM1: U1.18(GPA3) ; port GPIO0_CAM1
GPIO0_CAM2: U1.3(GPB3) ; port GPIO0_CAM2
GPIO0_CAM3: U4.18(GPA3) ; port GPIO0_CAM3
GPIO0_CAM4: U4.3(GPB3) ; port GPIO0_CAM4
GPIO0_CAM5: U5.18(GPA3) ; port GPIO0_CAM5
GPIO0_CAM6: U5.3(GPB3) ; port GPIO0_CAM6
MODE1_CAM1: U1.15(GPA0) ; port MODE1_CAM1
MODE1_CAM2: U1.24(GPB0) ; port MODE1_CAM2
MODE1_CAM3: U4.15(GPA0) ; port MODE1_CAM3
MODE1_CAM4: U4.24(GPB0) ; port MODE1_CAM4
MODE1_CAM5: U5.15(GPA0) ; port MODE1_CAM5
MODE1_CAM6: U5.24(GPB0) ; port MODE1_CAM6
MODE2_CAM1: U1.16(GPA1) ; port MODE2_CAM1
MODE2_CAM2: U1.1(GPB1) ; port MODE2_CAM2
MODE2_CAM3: U4.16(GPA1) ; port MODE2_CAM3
MODE2_CAM4: U4.1(GPB1) ; port MODE2_CAM4
MODE2_CAM5: U5.16(GPA1) ; port MODE2_CAM5
MODE2_CAM6: U5.1(GPB1) ; port MODE2_CAM6
MODE3_CAM1: U1.17(GPA2) ; port MODE3_CAM1
MODE3_CAM2: U1.2(GPB2) ; port MODE3_CAM2
MODE3_CAM3: U4.17(GPA2) ; port MODE3_CAM3
MODE3_CAM4: U4.2(GPB2) ; port MODE3_CAM4
MODE3_CAM5: U5.17(GPA2) ; port MODE3_CAM5
MODE3_CAM6: U5.2(GPB2) ; port MODE3_CAM6
OEN_CAM1: U1.20(GPA5) ; port OEN_CAM1
OEN_CAM2: U1.5(GPB5) ; port OEN_CAM2
OEN_CAM3: U4.20(GPA5) ; port OEN_CAM3
OEN_CAM4: U4.5(GPB5) ; port OEN_CAM4
OEN_CAM5: U5.20(GPA5) ; port OEN_CAM5
OEN_CAM6: U5.5(GPB5) ; port OEN_CAM6
PDB_CAM1: U1.22(GPA7) ; port PDB_CAM1
PDB_CAM2: U1.7(GPB7) ; port PDB_CAM2
PDB_CAM3: U4.22(GPA7) ; port PDB_CAM3
PDB_CAM4: U4.7(GPB7) ; port PDB_CAM4
PDB_CAM5: U5.22(GPA7) ; port PDB_CAM5
PDB_CAM6: U5.7(GPB7) ; port PDB_CAM6
SEL_CAM1: U1.21(GPA6) ; port SEL_CAM1
SEL_CAM2: U1.6(GPB6) ; port SEL_CAM2
SEL_CAM3: U4.21(GPA6) ; port SEL_CAM3
SEL_CAM5: U5.21(GPA6) ; port SEL_CAM5
SEL_CAM6: U5.6(GPB6) ; port SEL_CAM6
NetR2_1: R2.1 R3.1 U1.11(ADDR)
NetR4_1: R4.1 U1.12(~{RESET})
NetR5_2: R5.2 U3.1(A0)
NetR6_1: R6.1 U3.2(A1)
NetR7_1: R7.1 R8.1 U4.11(ADDR)
NetR9_1: R9.1 U4.12(~{RESET})
NetR10_1: R10.1 R11.1 U5.11(ADDR)
NetR12_1: R12.1 U5.12(~{RESET})
NetR185_1: R185.1 U1.9(SCL)
NetR186_1: R186.1 U1.10(SDA)
NetR187_1: R187.1 U4.10(SDA)
NetR188_1: R188.1 U4.9(SCL)
NetR189_1: R189.1 U5.9(SCL)
NetR190_1: R190.1 U5.10(SDA)

Not connected (* = marked no-connect by the designer): U1 13(INTB) 14(INTA); U2 3(NC)*; U4 13(INTB) 14(INTA); U5 13(INTB) 14(INTA)

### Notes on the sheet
- COMMON
- STATUS &  CONTROL
  CAMERA 1 & 2
- I2C ACCELERATOR
- INFO EEPROM
- Address = 0x4E
- STATUS & CONTROL
  CAMERA 3 & 4
- Address = 0x41
- CONFIGURATION SELECT
  - 6 Channels (D9-D2 + HS + VS + CLK)
  - 6 Channels (D9-D0 + HS  + CLK)
  - 4 Channels (D11-D0 + HS + VS + CLK)
- Address = 0x4A
- STATUS & CONTROL
  CAMERA 5 & 6

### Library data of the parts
C2-C6 = GRM155R71C104KA88D: CAP, CERM, 0.1uF, 16V, +/-10%, X7R, 0402; Manufacturer: MuRata; Polarized: N; CompType: Capacitor; U/M: EA; Cap_F: 0.0000001; Tolerance_%: 10; Value1: Unknown; VDC_V: 16; TaMin_C: -55; TaMax_C: 125; Cap_Case: 0402
CN2-CN4 = 3X6 Header 100 MIL PITCH
R2 = CRCW04021K00FKED: as R13 on sheet POWER
R3 = CRCW040215K0FKED: RES, 15.0k ohm, 1%, 0.063W, 0402; Manufacturer: Vishay-Dale; CompType: Resistor; Res_ohm: 15000; Value_Code: 15k0; Tolerance_%: 1; Power_W: 0.063; VDC_V: 50; TempCo: 100 ppm/C; EIA_Code: E96; U/M: EA
R4-R6 R9 R12 = CRCW040210K0FKED: as R17 on sheet POWER
R7 = CRCW040213K0FKED: RES, 13.0k ohm, 1%, 0.063W, 0402; Manufacturer: Vishay-Dale; CompType: Resistor; Res_ohm: 13000; Value_Code: 13k0; Tolerance_%: 1; Power_W: 0.063; VDC_V: 50; TempCo: 100 ppm/C; EIA_Code: E96; U/M: EA
R8 = CRCW04023K01FKED: RES, 3.01k ohm, 1%, 0.063W, 0402; Manufacturer: Vishay-Dale; CompType: Resistor; Res_ohm: 3010; Value_Code: 3k01; Tolerance_%: 1; Power_W: 0.063; VDC_V: 50; TempCo: 100 ppm/C; EIA_Code: E96; U/M: EA
R10 = CRCW04024K99FKED: RES, 4.99k ohm, 1%, 0.063W, 0402; Manufacturer: Vishay-Dale; CompType: Resistor; Res_ohm: 4990; Value_Code: 4k99; Tolerance_%: 1; Power_W: 0.063; VDC_V: 50; TempCo: 100 ppm/C; EIA_Code: E96; U/M: EA
R11 = CRCW040211K0FKED: RES, 11.0k ohm, 1%, 0.063W, 0402; Manufacturer: Vishay-Dale; CompType: Resistor; Res_ohm: 11000; Value_Code: 11k0; Tolerance_%: 1; Power_W: 0.063; VDC_V: 50; TempCo: 100 ppm/C; EIA_Code: E96; U/M: EA
R185-R190 = CRCW040233R0JNED: RES, 33 ohm, 5%, 0.063W, 0402; Manufacturer: Vishay-Dale; CompType: Resistor; Value_Code: 33R0; Tolerance_%: 5; Power_W: 0.063; VDC_V: 50; TempCo: 200 ppm/C; EIA_Code: E24; U/M: EA
U1 U4 U5 = MCP23018-E/MJ: IC I/O EXPANDER I2C 16B 24QFN; Manufacturer: Microchip Technology; Number of I /O: 16; Interface: I²C; Interrupt Output: Yes; Output Type: Open Drain; Current - Output Source/Sink: 25mA; Frequency - Clock: 3.4MHz; Voltage - Supply: 1.8 V ~ 5.5 V
U2 = LTC1694-1IS5#TRMPBF: IC ACCEL SMBUS DUAL TSOT23-5; Manufacturer: Linear Technology; Interface: SMBus (2-Wire/I²C); Voltage - Supply: 2.7 V ~ 6 V
U3 = AT24C02BN-SH-B: IC EEPROM 2KBIT 1MHZ 8SOIC; Manufacturer: Atmel; Format - Memory: EEPROMs - Serial; Memory Size: 2K (256 x 8); Speed: 400kHz, 1MHz; Interface: I²C, 2-Wire Serial; Voltage - Supply: 1.8 V ~ 5.5 V

## Sheet CAMERA 1.SchDoc
size 431 x 279 mm; Date: Not shown in title block; ApprovedBy: Not shown in title block; CheckedBy: Not shown in title block; Author: Not shown in title block; CompanyName: Not shown in title block; DrawnBy: G. Fiolic; Engineer: Not shown in title block; Organization: Not shown in title block; Address1: Not shown in title block; Address2: Not shown in title block; Address3: Not shown in title block; Address4: Not shown in title block; DocumentNumber: 5; Revision: Use project parameter SCH_Rev; SheetNumber: 5; SheetTotal: 11; PageSetup: Record=PageOptions|CenterHorizontal=True|CenterVertical=True|PrintScale=1.00|XCorrection=1.00|YCorrection=1.00|PrintKind=0|BorderSize=5000000|LeftOffset=0|BottomOffset=0|Orientation=2|PaperLength=1000|PaperWidth=1000|Scale=100|PaperSource=15|PrintQuality=600|MediaType=1|DitherType=10|PaperKind=Letter|PrintScaleMode=1
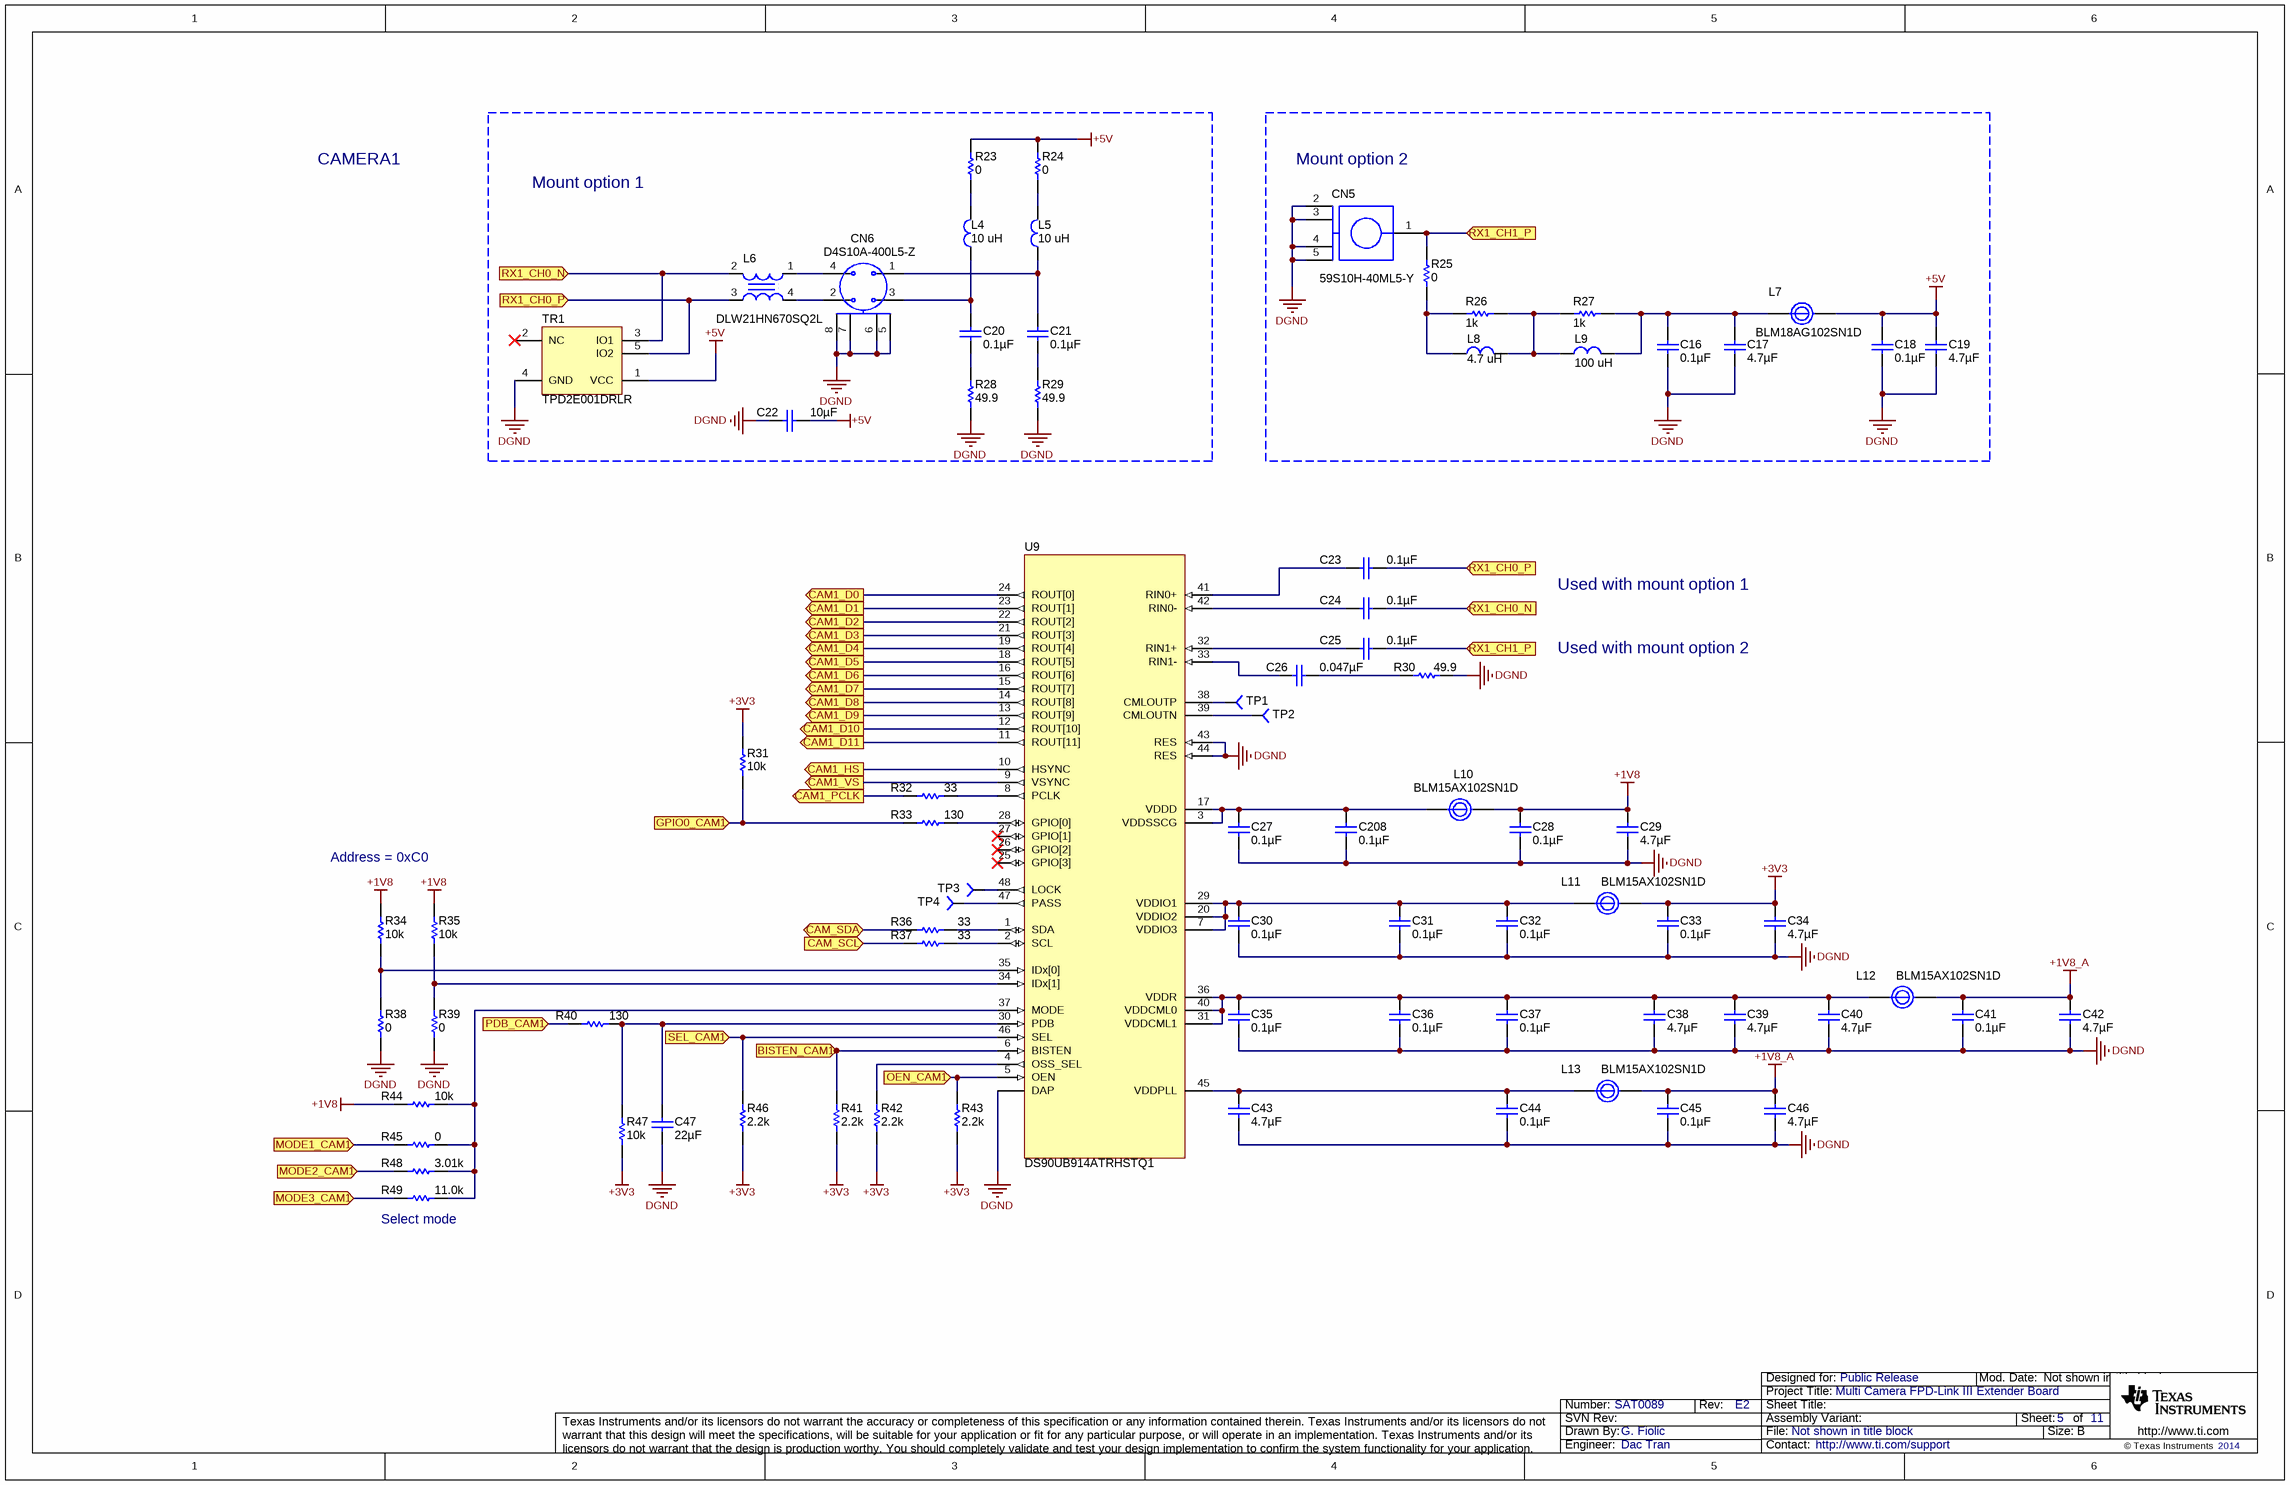
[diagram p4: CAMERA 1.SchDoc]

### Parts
C16  ValueDisplayed: 0.1µF  [0402L]  (hidden comment: GRM155R71C104KA88D)
C17  value 4.7µF  [0603L]  (hidden comment: GRM188R61E475KE11D)
C18  ValueDisplayed: 0.1µF  [0402L]  (hidden comment: GRM155R71C104KA88D)
C19  value 4.7µF  [0603L]  (hidden comment: GRM188R61E475KE11D)
C20  value 0.1µF  [0603L]  (hidden comment: GRM188R72A104KA35D)
C21  value 0.1µF  [0603L]  (hidden comment: GRM188R72A104KA35D)
C22  ValueDisplayed: 10µF  [0805L]  (hidden comment: GRM21BR61C106KE15L)
C23  ValueDisplayed: 0.1µF  [0402L]  (hidden comment: GRM155R71C104KA88D)
C24  ValueDisplayed: 0.1µF  [0402L]  (hidden comment: GRM155R71C104KA88D)
C25  ValueDisplayed: 0.1µF  [0402L]  (hidden comment: GRM155R71C104KA88D)
C26  ValueDisplayed: 0.047µF  [0402L]  (hidden comment: GRM155R71C473KA01D)
C27  ValueDisplayed: 0.1µF  [0402L]  (hidden comment: GRM155R71C104KA88D)
C28  ValueDisplayed: 0.1µF  [0402L]  (hidden comment: GRM155R71C104KA88D)
C29  value 4.7µF  [0603L]  (hidden comment: GRM188R61E475KE11D)
C30  ValueDisplayed: 0.1µF  [0402L]  (hidden comment: GRM155R71C104KA88D)
C31  ValueDisplayed: 0.1µF  [0402L]  (hidden comment: GRM155R71C104KA88D)
C32  ValueDisplayed: 0.1µF  [0402L]  (hidden comment: GRM155R71C104KA88D)
C33  ValueDisplayed: 0.1µF  [0402L]  (hidden comment: GRM155R71C104KA88D)
C34  value 4.7µF  [0603]  (hidden comment: GRM188R61E475KE11D)
C35  ValueDisplayed: 0.1µF  [0402L]  (hidden comment: GRM155R71C104KA88D)
C36  ValueDisplayed: 0.1µF  [0402L]  (hidden comment: GRM155R71C104KA88D)
C37  ValueDisplayed: 0.1µF  [0402L]  (hidden comment: GRM155R71C104KA88D)
C38  value 4.7µF  [0603L]  (hidden comment: GRM188R61E475KE11D)
C39  value 4.7µF  [0603L]  (hidden comment: GRM188R61E475KE11D)
C40  value 4.7µF  [0603L]  (hidden comment: GRM188R61E475KE11D)
C41  ValueDisplayed: 0.1µF  [0402L]  (hidden comment: GRM155R71C104KA88D)
C42  value 4.7µF  [0603L]  (hidden comment: GRM188R61E475KE11D)
C43  value 4.7µF  [0603L]  (hidden comment: GRM188R61E475KE11D)
C44  ValueDisplayed: 0.1µF  [0402L]  (hidden comment: GRM155R71C104KA88D)
C45  ValueDisplayed: 0.1µF  [0402L]  (hidden comment: GRM155R71C104KA88D)
C46  value 4.7µF  [0603L]  (hidden comment: GRM188R61E475KE11D)
C47  ValueDisplayed: 22µF  [0805L]  (hidden comment: JMK212BJ226KG-T)
C208  ValueDisplayed: 0.1µF  [0402L]  (hidden comment: GRM155R71C104KA88D)
CN5  59S10H-40ML5-Y  [59S10H-40ML5-Y]
CN6  D4S10A-400L5-Z  [D4S10A-400L5-Z]
L4  ValueDisplayed: 10 uH  [1008PS-103KLB]  (hidden comment: 1008PS-103KLB)
L5  ValueDisplayed: 10 uH  [1008PS-103KLB]  (hidden comment: 1008PS-103KLB)
L6  DLW21HN670SQ2L  [DLW21HN670SQ2L]
L7  BLM18AG102SN1D  [0603L]
L8  ValueDisplayed: 4.7 uH  [1008PS-472KLB]  (hidden comment: 1008PS-472KLB)
L9  ValueDisplayed: 100 uH  [MSS7341T-104MLB]  (hidden comment: MSS7341T-104MLB)
L10  BLM15AX102SN1D  [0402L]
L11  BLM15AX102SN1D  [0402L]
L12  BLM15AX102SN1D  [0402L]
L13  BLM15AX102SN1D  [0402L]
R23  value 0  [0805L]  (hidden comment: CRCW08050000Z0EA)
R24  value 0  [0805L]  (hidden comment: CRCW08050000Z0EA)
R25  value 0  [0805L]  (hidden comment: CRCW08050000Z0EA)
R26  value 1k  [0603L]  (hidden comment: RC0603JR-071KL)
R27  value 1k  [0603L]  (hidden comment: RC0603JR-071KL)
R28  value 49.9  [0402L]  (hidden comment: CRCW040249R9FKED)
R29  value 49.9  [0402L]  (hidden comment: CRCW040249R9FKED)
R30  value 49.9  [0402L]  (hidden comment: CRCW040249R9FKED)
R31  value 10k  [0402L]  (hidden comment: ERA-2AEB103X)
R32  value 33  [0402L]  (hidden comment: CRCW040233R0JNED)
R33  value 130  [0402L]  (hidden comment: CRCW0402130RJNED)
R34  value 10k  [0402L]  (hidden comment: ERA-2AEB103X)
R35  value 10k  [0402L]  (hidden comment: ERA-2AEB103X)
R36  value 33  [0402L]  (hidden comment: CRCW040233R0JNED)
R37  value 33  [0402L]  (hidden comment: CRCW040233R0JNED)
R38  value 0  [0402L]  (hidden comment: CRCW04020000Z0ED)
R39  value 0  [0402L]  (hidden comment: CRCW04020000Z0ED)
R40  value 130  [0402L]  (hidden comment: CRCW0402130RJNED)
R41  value 2.2k  [0402L]  (hidden comment: CRCW04022K20JNED)
R42  value 2.2k  [0402L]  (hidden comment: CRCW04022K20JNED)
R43  value 2.2k  [0402L]  (hidden comment: CRCW04022K20JNED)
R44  value 10k  [0402L]  (hidden comment: ERA-2AEB103X)
R45  value 0  [0402L]  (hidden comment: CRCW04020000Z0ED)
R46  value 2.2k  [0402L]  (hidden comment: CRCW04022K20JNED)
R47  value 10k  [0402L]  (hidden comment: ERA-2AEB103X)
R48  value 3.01k  [0402L]  (hidden comment: CRCW04023K01FKED)
R49  value 11.0k  [0402L]  (hidden comment: CRCW040211K0FKED)
TP1  STD  [TP-032_RND]  (value not drawn)
TP2  STD  [TP-032_RND]  (value not drawn)
TP3  STD  [TP-032_RND]  (value not drawn)
TP4  STD  [TP-032_RND]  (value not drawn)
TR1  TPD2E001DRLR  [DRL0005A]
U9  DS90UB914ATRHSTQ1  [RHS0048A]

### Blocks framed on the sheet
Mount option 1: C20-C22 CN6 L4-L6 R23 R24 R28 R29 TR1

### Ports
BISTEN_CAM1 (in), CAM1_D0 (out), CAM1_D1 (out), CAM1_D2 (out), CAM1_D3 (out), CAM1_D4 (out), CAM1_D5 (out), CAM1_D6 (out), CAM1_D7 (out), CAM1_D8 (out), CAM1_D9 (out), CAM1_D10 (out), CAM1_D11 (out), CAM1_HS (out), CAM1_PCLK (out), CAM1_VS (out), CAM_SCL (in), CAM_SDA (bidir), GPIO0_CAM1 (in), MODE1_CAM1 (in), MODE2_CAM1 (in), MODE3_CAM1 (in), OEN_CAM1 (in), PDB_CAM1 (in), RX1_CH0_N (in), RX1_CH0_P (in), RX1_CH1_P (in), SEL_CAM1 (in)

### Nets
+1V8: C28.1 C29.1 L10.2 R34.1 R35.1 R44.1
+1V8_A: C41.1 C42.1 C45.1 C46.1 L12.2 L13.2
+3V3: C33.1 C34.1 L11.2 R31.1 R41.2 R42.2 R43.2 R46.1 R47.1
+5V: C18.1 C19.1 C22.1 L7.2 R23.2 R24.2 TR1.1(VCC)
DGND: C16.2 C17.2 C18.2 C19.2 C22.2 C27.2 C28.2 C29.2 C30.2 C31.2 C32.2 C33.2 C34.2 C35.2 C36.2 C37.2 C38.2 C39.2 C40.2 C41.2 C42.2 C43.2 C44.2 C45.2 C46.2 C47.2 C208.2 CN5.2 CN5.3 CN5.4 CN5.5 CN6.5 CN6.6 CN6.7 CN6.8 R28.1 R29.1 R30.2 R38.2 R39.2 TR1.4(GND) U9.43(RES) U9.44(RES) U9.49(DAP)
BISTEN_CAM1: R41.1 U9.6(BISTEN) ; port BISTEN_CAM1
CAM1_D0: U9.24(ROUT[0]) ; port CAM1_D0
CAM1_D1: U9.23(ROUT[1]) ; port CAM1_D1
CAM1_D2: U9.22(ROUT[2]) ; port CAM1_D2
CAM1_D3: U9.21(ROUT[3]) ; port CAM1_D3
CAM1_D4: U9.19(ROUT[4]) ; port CAM1_D4
CAM1_D5: U9.18(ROUT[5]) ; port CAM1_D5
CAM1_D6: U9.16(ROUT[6]) ; port CAM1_D6
CAM1_D7: U9.15(ROUT[7]) ; port CAM1_D7
CAM1_D8: U9.14(ROUT[8]) ; port CAM1_D8
CAM1_D9: U9.13(ROUT[9]) ; port CAM1_D9
CAM1_D10: U9.12(ROUT[10]) ; port CAM1_D10
CAM1_D11: U9.11(ROUT[11]) ; port CAM1_D11
CAM1_HS: U9.10(HSYNC) ; port CAM1_HS
CAM1_PCLK: R32.1 ; port CAM1_PCLK
CAM1_VS: U9.9(VSYNC) ; port CAM1_VS
CAM_SCL: R37.1 ; port CAM_SCL
CAM_SDA: R36.2 ; port CAM_SDA
GPIO0_CAM1: R31.2 R33.1 ; port GPIO0_CAM1
MODE1_CAM1: R45.1 ; port MODE1_CAM1
MODE2_CAM1: R48.1 ; port MODE2_CAM1
MODE3_CAM1: R49.1 ; port MODE3_CAM1
OEN_CAM1: R43.1 U9.5(OEN) ; port OEN_CAM1
PDB_CAM1: R40.1 ; port PDB_CAM1
RX1_CH0_N: C24.2 L6.2(IN2) TR1.3(IO1) ; port RX1_CH0_N
RX1_CH0_P: C23.2 L6.3(OUT2) TR1.5(IO2) ; port RX1_CH0_P
RX1_CH1_P: C25.2 CN5.1 R25.2 ; port RX1_CH1_P
SEL_CAM1: R46.2 U9.46(SEL) ; port SEL_CAM1
NetC16_1: C16.1 C17.1 L7.1 L9.2 R27.2
NetC20_1: C20.1 CN6.3 L4.1
NetC20_2: C20.2 R28.2
NetC21_1: C21.1 CN6.1 L5.1
NetC21_2: C21.2 R29.2
NetC23_1: C23.1 U9.41(RIN0+)
NetC24_1: C24.1 U9.42(RIN0-)
NetC25_1: C25.1 U9.32(RIN1+)
NetC26_1: C26.1 R30.1
NetC26_2: C26.2 U9.33(RIN1-)
NetC27_1: C27.1 C208.1 L10.1 U9.3(VDDSSCG) U9.17(VDDD)
NetC30_1: C30.1 C31.1 C32.1 L11.1 U9.7(VDDIO3) U9.20(VDDIO2) U9.29(VDDIO1)
NetC35_1: C35.1 C36.1 C37.1 C38.1 C39.1 C40.1 L12.1 U9.31(VDDCML1) U9.36(VDDR) U9.40(VDDCML0)
NetC43_1: C43.1 C44.1 L13.1 U9.45(VDDPLL)
NetC47_1: C47.1 R40.2 R47.2 U9.30(PDB)
NetCN6_2: CN6.2 L6.4(OUT1)
NetCN6_4: CN6.4 L6.1(IN1)
NetL4_2: L4.2 R23.1
NetL5_2: L5.2 R24.1
NetL8_1: L8.1 R25.1 R26.1
NetL8_2: L8.2 L9.1 R26.2 R27.1
NetR32_2: R32.2 U9.8(PCLK)
NetR33_2: R33.2 U9.28(GPIO[0])
NetR34_2: R34.2 R38.1 U9.35(IDx[0])
NetR35_2: R35.2 R39.1 U9.34(IDx[1])
NetR36_1: R36.1 U9.1(SDA)
NetR37_2: R37.2 U9.2(SCL)
NetR42_1: R42.1 U9.4(OSS_SEL)
NetR44_2: R44.2 R45.2 R48.2 R49.2 U9.37(MODE)
NetTP1_1: TP1.1 U9.38(CMLOUTP)
NetTP2_1: TP2.1 U9.39(CMLOUTN)
NetTP3_1: TP3.1 U9.48(LOCK)
NetTP4_1: TP4.1 U9.47(PASS)

Not connected (* = marked no-connect by the designer): TR1 2(NC)*; U9 25(GPIO[3])* 26(GPIO[2])* 27(GPIO[1])*

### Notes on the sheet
- CAMERA1
- (near CN5) Mount option 2
- Used with mount option 1
- Used with mount option 2
- Address = 0xC0
- (near R49) Select mode

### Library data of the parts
C16 C18 C23-C25 C27 C28 C30-C33 C35-C37 C41 C44 C45 C208 = GRM155R71C104KA88D: as C2 on sheet COMMON
C17 C19 C29 C34 C38-C40 C42 C43 C46 = GRM188R61E475KE11D: CAP CER 4.7UF 25V 10% X5R 0603; Manufacturer: Murata Electronics North America
C20 C21 = GRM188R72A104KA35D: CAP CER 0.1UF 100V 10% X7R 0603; Manufacturer: Murata Electronics North America
C22 = GRM21BR61C106KE15L: CAP, CERM, 10uF, 16V, +/-10%, X5R, 0805; Manufacturer: MuRata; Polarized: N; CompType: Capacitor; U/M: EA; Cap_F: 0.00001; Tolerance_%: 10; ESR_Ohm: 0.008; Value1: 0.008 ohm; VDC_V: 16; TaMin_C: -55; TaMax_C: 85; Cap_Case: 0805
C26 = GRM155R71C473KA01D: CAP, CERM, 0.047uF, 16V, +/-10%, X7R, 0402; Manufacturer: MuRata; Polarized: N; CompType: Capacitor; U/M: EA; Cap_F: 0.000000047; Tolerance_%: 10; Value1: Unknown; VDC_V: 16; TaMin_C: -55; TaMax_C: 125; Cap_Case: 0402
C47 = JMK212BJ226KG-T: CAP, CERM, 22uF, 6.3V, +/-10%, X5R, 0805; Manufacturer: Taiyo Yuden; Polarized: N; CompType: Capacitor; U/M: EA; Cap_F: 0.000022; Tolerance_%: 10; ESR_Ohm: 0.002; Value1: 0.002 ohm; VDC_V: 6.3; TaMin_C: -55; TaMax_C: 85; Cap_Case: 0805
CN5 = 59S10H-40ML5-Y: Straight Plug PCB; Manufacturer: Rosenberger; SymbolVersion: use current date i.e. 2008-05-20; SymbolCreator: Use a-id; CompType: SMA connector; U/M: EA, IN, or GM
CN6 = D4S10A-400L5-Z: Straight Plug; Manufacturer: Rosenberger
L4 L5 = 1008PS-103KLB: Fixed Inductors Power Inductor 10 uH 10 % 0.59 A; Manufacturer: Coilcraft; Material: Ferrite; Maximum DC Current: 590 mA; Maximum DC Resistance: 920 mOhms; Q Minimum: 38; Self Resonant Frequency: 105 MHz; Shielding: Shielded; Tolerance_%: 10 %; Case Height: 2.74 mm; Case Length: 3.81 mm; Case Width: 3.78 mm; Test Frequency: 100 kHz; Product Status: New at Mouser
L6 = DLW21HN670SQ2L: CHOKE COMMON MODE 67 OHM 0805; Manufacturer: Murata Electronics North America; Filter Type: Data, Signal Line; Number of Lines: 2; Irms: 330mA; DCR_Ohm: 350 mOhm Max; Impedance: 67 Ohm
L7 = BLM18AG102SN1D: FERRITE CHIP 1000 OHM 400MA 0603; Manufacturer: Murata Electronics North America; Impedance @ Frequency: 1 kOhm @ 100MHz; DCR_Ohm: 500 mOhm Max; Filter Type: Differential Mode - Single
L8 = 1008PS-472KLB: Fixed Inductors Power Inductor 4.7 uH 10 % 0.95 A; Manufacturer: Coilcraft; Material: Ferrite; Maximum DC Current: 950 mA; Maximum DC Resistance: 350 mOhms; Q Minimum: 38; Self Resonant Frequency: 160 MHz; Shielding: Shielded; Tolerance_%: 10 %; Case Height: 2.74 mm; Case Length: 3.81 mm; Case Width: 3.78 mm; Test Frequency: 100 kHz
L9 = MSS7341T-104MLB: Fixed Inductors Power Inductor 100 uH 20 % 1.15 A; Manufacturer: Coilcraft; Material: Ferrite; Maximum DC Current: 1.15 A; Maximum DC Resistance: 310 mOhms; Self Resonant Frequency: 7.2 MHz; Shielding: Shielded; Tolerance_%: 20 %; Case Height: 4.1 mm; Case Length: 7.3 mm; Test Frequency: 100 kHz
L10-L13 = BLM15AX102SN1D: FERRITE CHIP 1000 OHM 0402; Manufacturer: Murata Electronics North America; Impedance @ Frequency: 1 kOhm @ 100MHz; Current Rating: 350mA; DCR_Ohm: 490 mOhm Max; Filter Type: Differential Mode - Single
R23-R25 = CRCW08050000Z0EA: RES, 0 ohm, 5%, 0.125W, 0805; Manufacturer: Vishay-Dale; CompType: Resistor; Value_Code: 0000; Tolerance_%: 5; Power_W: 0.125; VDC_V: 150; TempCo: 200 ppm/C; EIA_Code: E24; U/M: EA
R26 R27 = RC0603JR-071KL: RES 1.0K OHM 1/10W 5% 0603 SMD; Manufacturer: Yageo; Power_W: 0.1W, 1/10W; TempCo: ±100ppm/°C
R28-R30 = CRCW040249R9FKED: RES, 49.9 ohm, 1%, 0.063W, 0402; Manufacturer: Vishay-Dale; CompType: Resistor; Value_Code: 49R9; Tolerance_%: 1; Power_W: 0.063; VDC_V: 50; TempCo: 100 ppm/C; EIA_Code: E96; U/M: EA
R31 R34 R35 R44 R47 = ERA-2AEB103X: RES 10K OHM 1/16W .1% 0402 SMD; Manufacturer: Panasonic Electronic Components; Tolerance_%: ±0.1%; Power_W: 0.063W, 1/16W; TempCo: ±25ppm/°C
R32 R36 R37 = CRCW040233R0JNED: as R185 on sheet COMMON
R33 R40 = CRCW0402130RJNED: RES, 130 ohm, 5%, 0.063W, 0402; Manufacturer: Vishay-Dale; CompType: Resistor; Value_Code: 130R; Tolerance_%: 5; Power_W: 0.063; VDC_V: 50; TempCo: 200 ppm/C; EIA_Code: E24; U/M: EA
R38 R39 R45 = CRCW04020000Z0ED: as R1 on sheet MAIN_CONNECTORS
R41-R43 R46 = CRCW04022K20JNED: RES, 2.2k ohm, 5%, 0.063W, 0402; Manufacturer: Vishay-Dale; CompType: Resistor; Res_ohm: 2200; Value_Code: 2k20; Tolerance_%: 5; Power_W: 0.063; VDC_V: 50; TempCo: 200 ppm/C; EIA_Code: E24; U/M: EA
R48 = CRCW04023K01FKED: as R8 on sheet COMMON
R49 = CRCW040211K0FKED: as R11 on sheet COMMON
TP1-TP4 = TP-032_RND: Test Point, O.032 Hole
TR1 = TPD2E001DRLR: Low-Capacitance + / - 15 kV ESD-Protection Array for High-Speed Data Interfaces, 2 Channels, -40 to +85 degC, 5-pin SOT (DRL), Green (RoHS & no Sb/Br); Manufacturer: Texas Instruments; Alternate Manufacturer: None; Alternate PartNumber: Equivalent; Breakdown Voltage(Min)(V): 11; IEC 61000-4-2 Air-Gap(+/- kV): 15; IEC 61000-4-2 Contact(+/- kV): 8; IO Capacitance(Typ)(pF): 1.5; IO Leakage Current(nA): 1; SubFamily: ESD Solution; USB High Speed: TRUE
U9 = DS90UB914ATRHSTQ1: FPD-Link III Serializer and Deserializer, RHS0048A; Alternate Manufacturer: None; Manufacturer: Texas Instruments; SymbolCreator: a0799628; CompType: IC; U/M: EA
